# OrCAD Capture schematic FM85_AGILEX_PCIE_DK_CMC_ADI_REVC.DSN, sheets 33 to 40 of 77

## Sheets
33 FPGA BANK 15C: size B
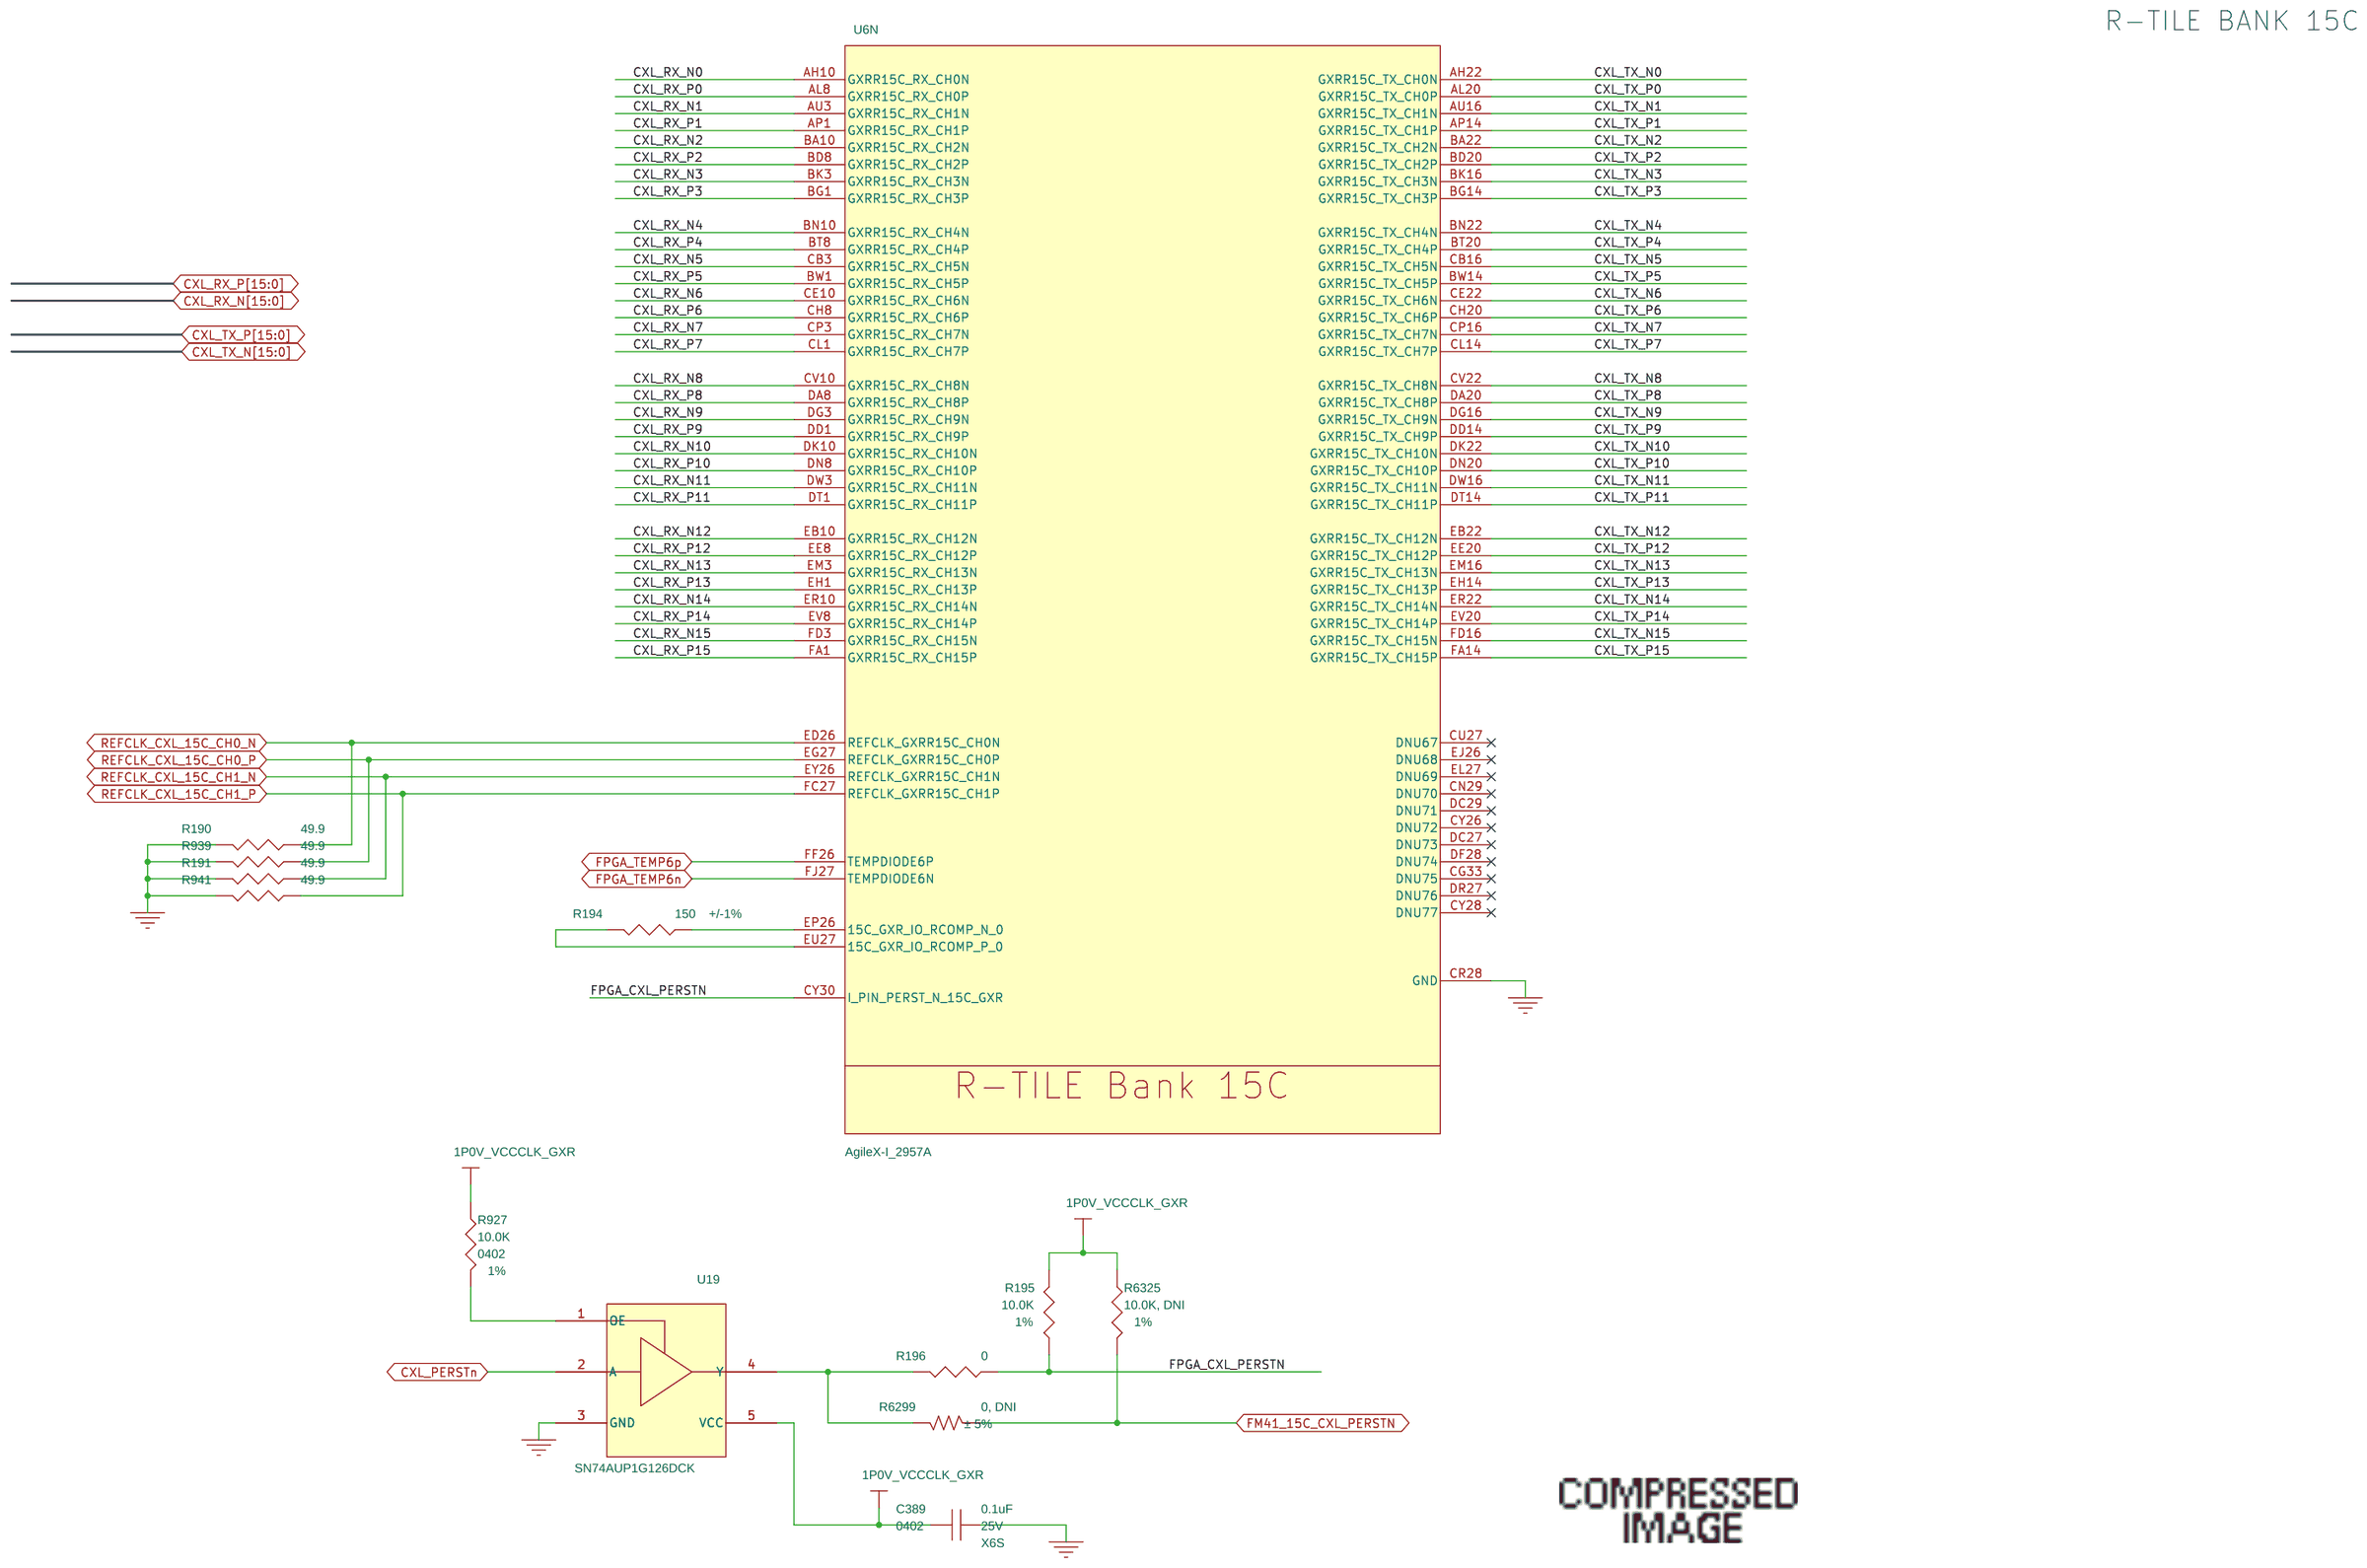
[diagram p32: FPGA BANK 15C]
34 FPGA BANK 15A: size B
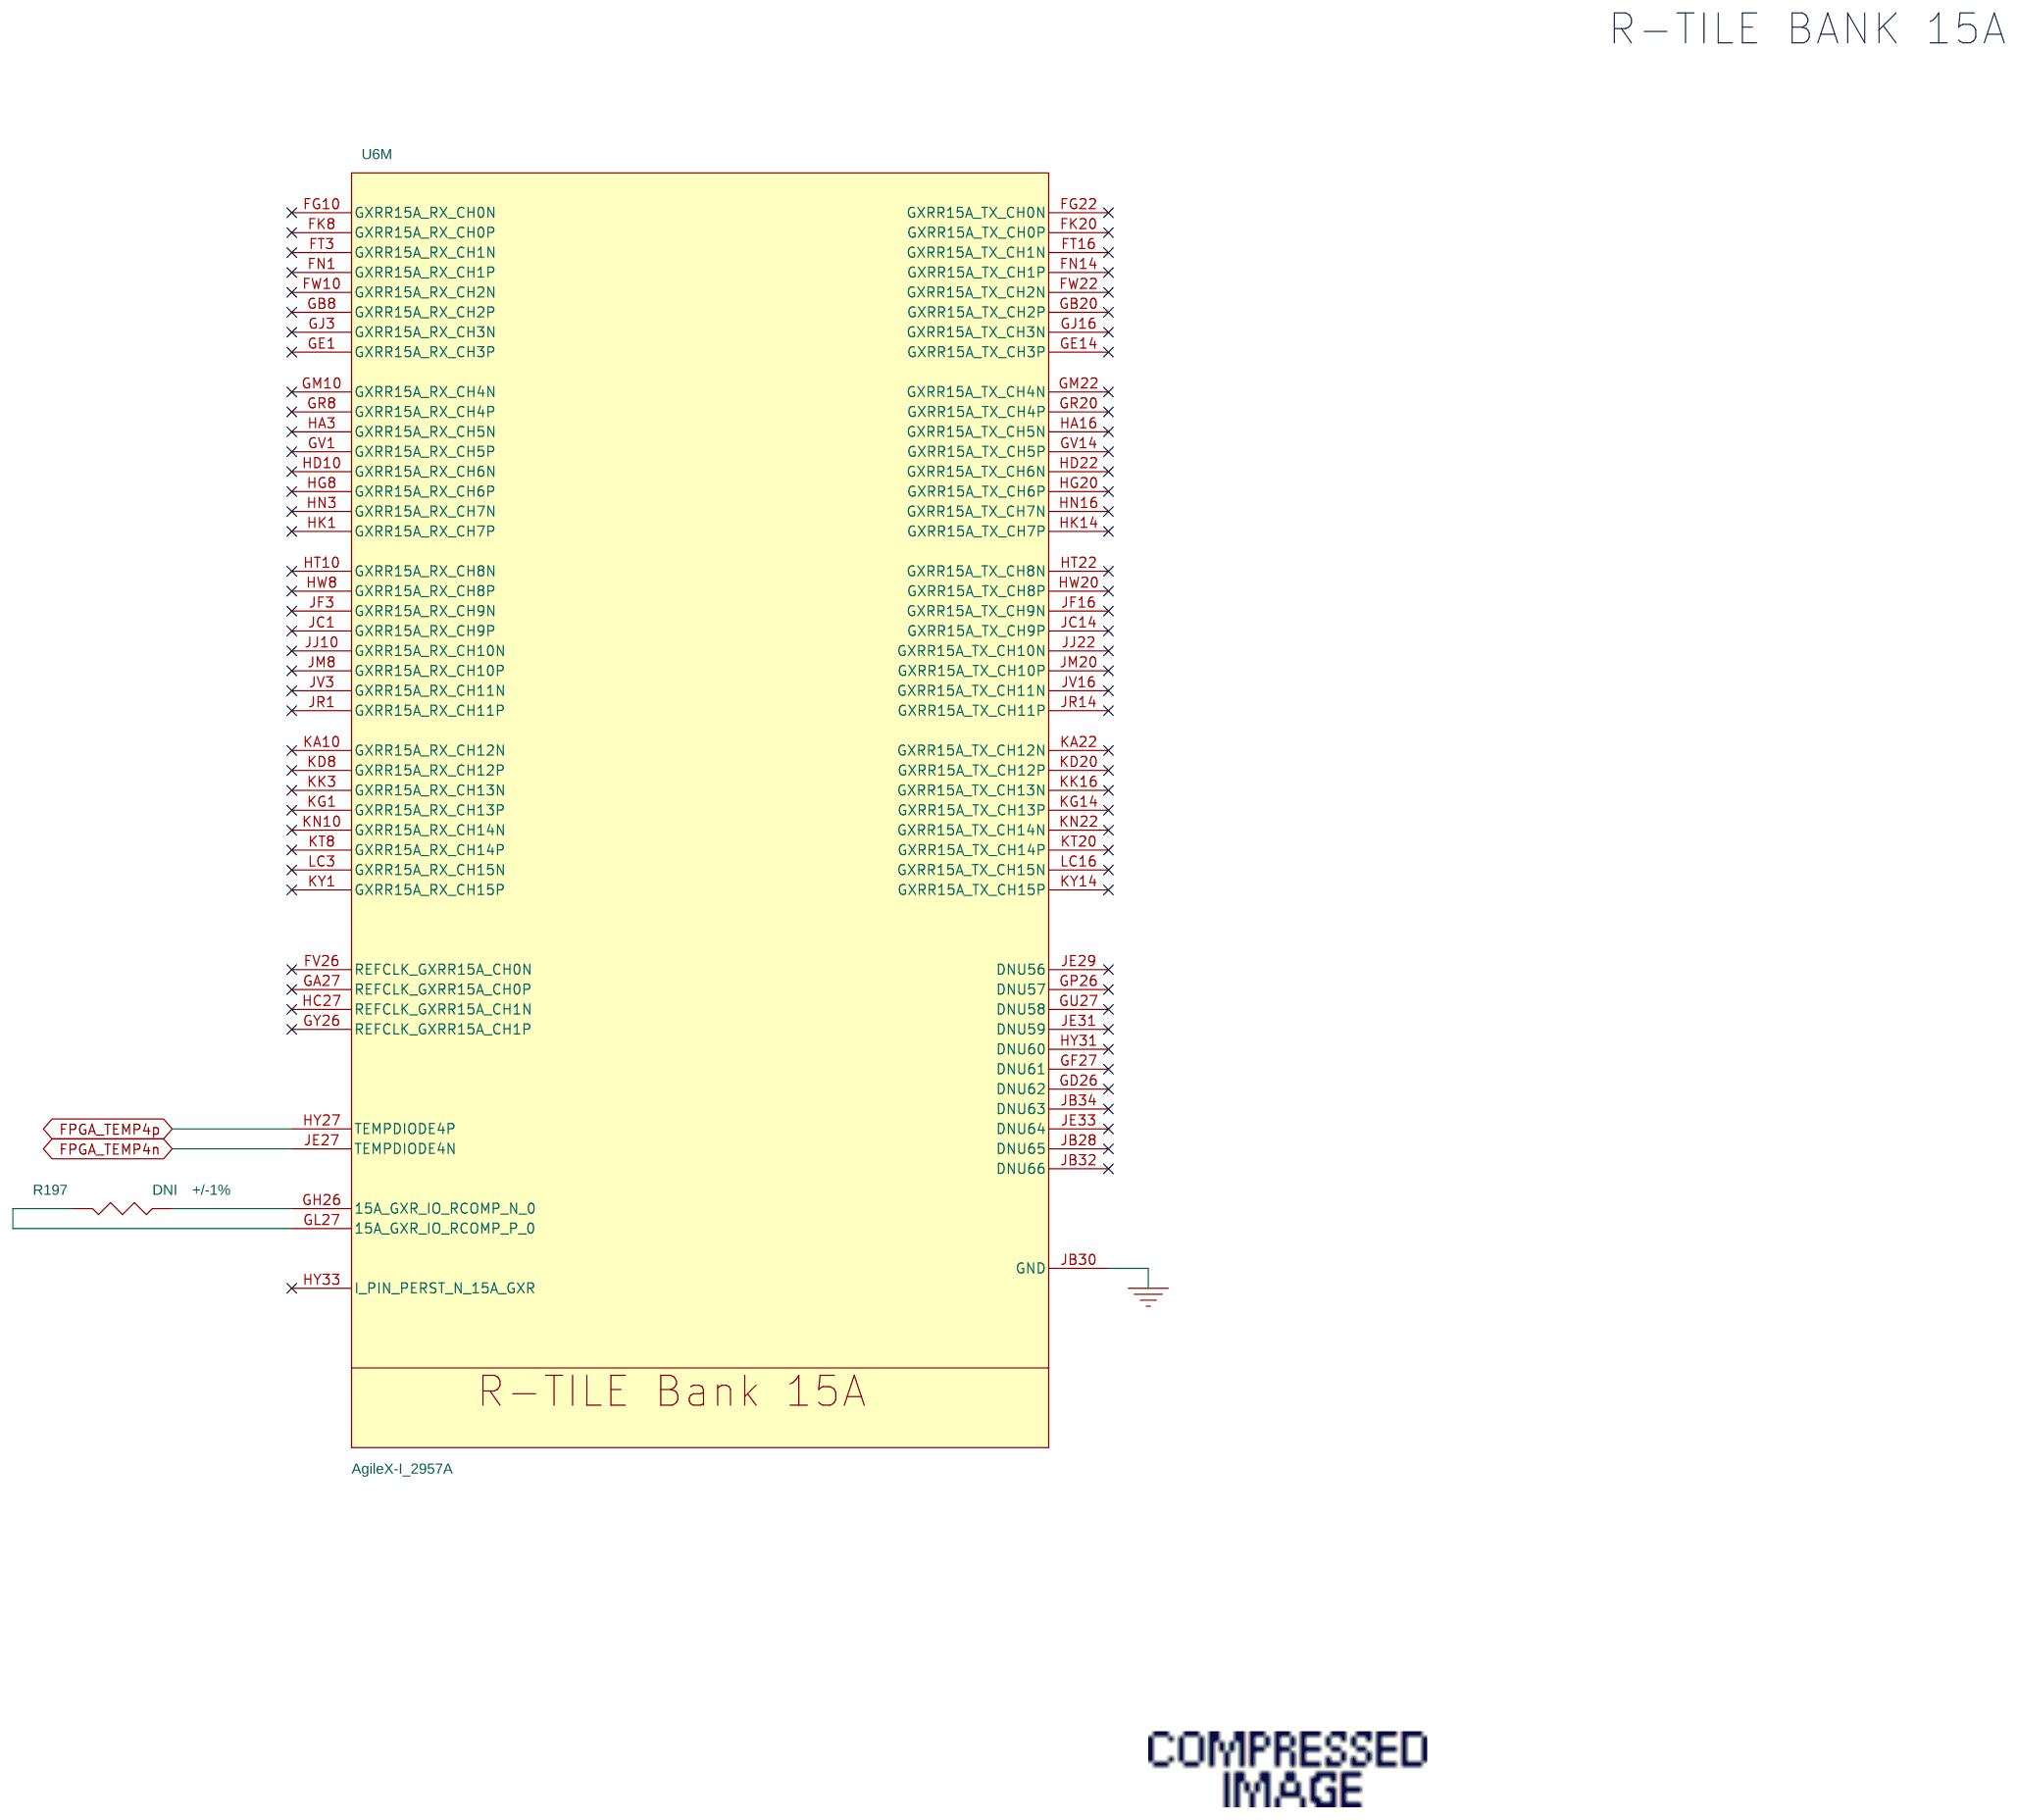
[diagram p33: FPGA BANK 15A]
35 FPGA BANK CONFIG SDM: size B
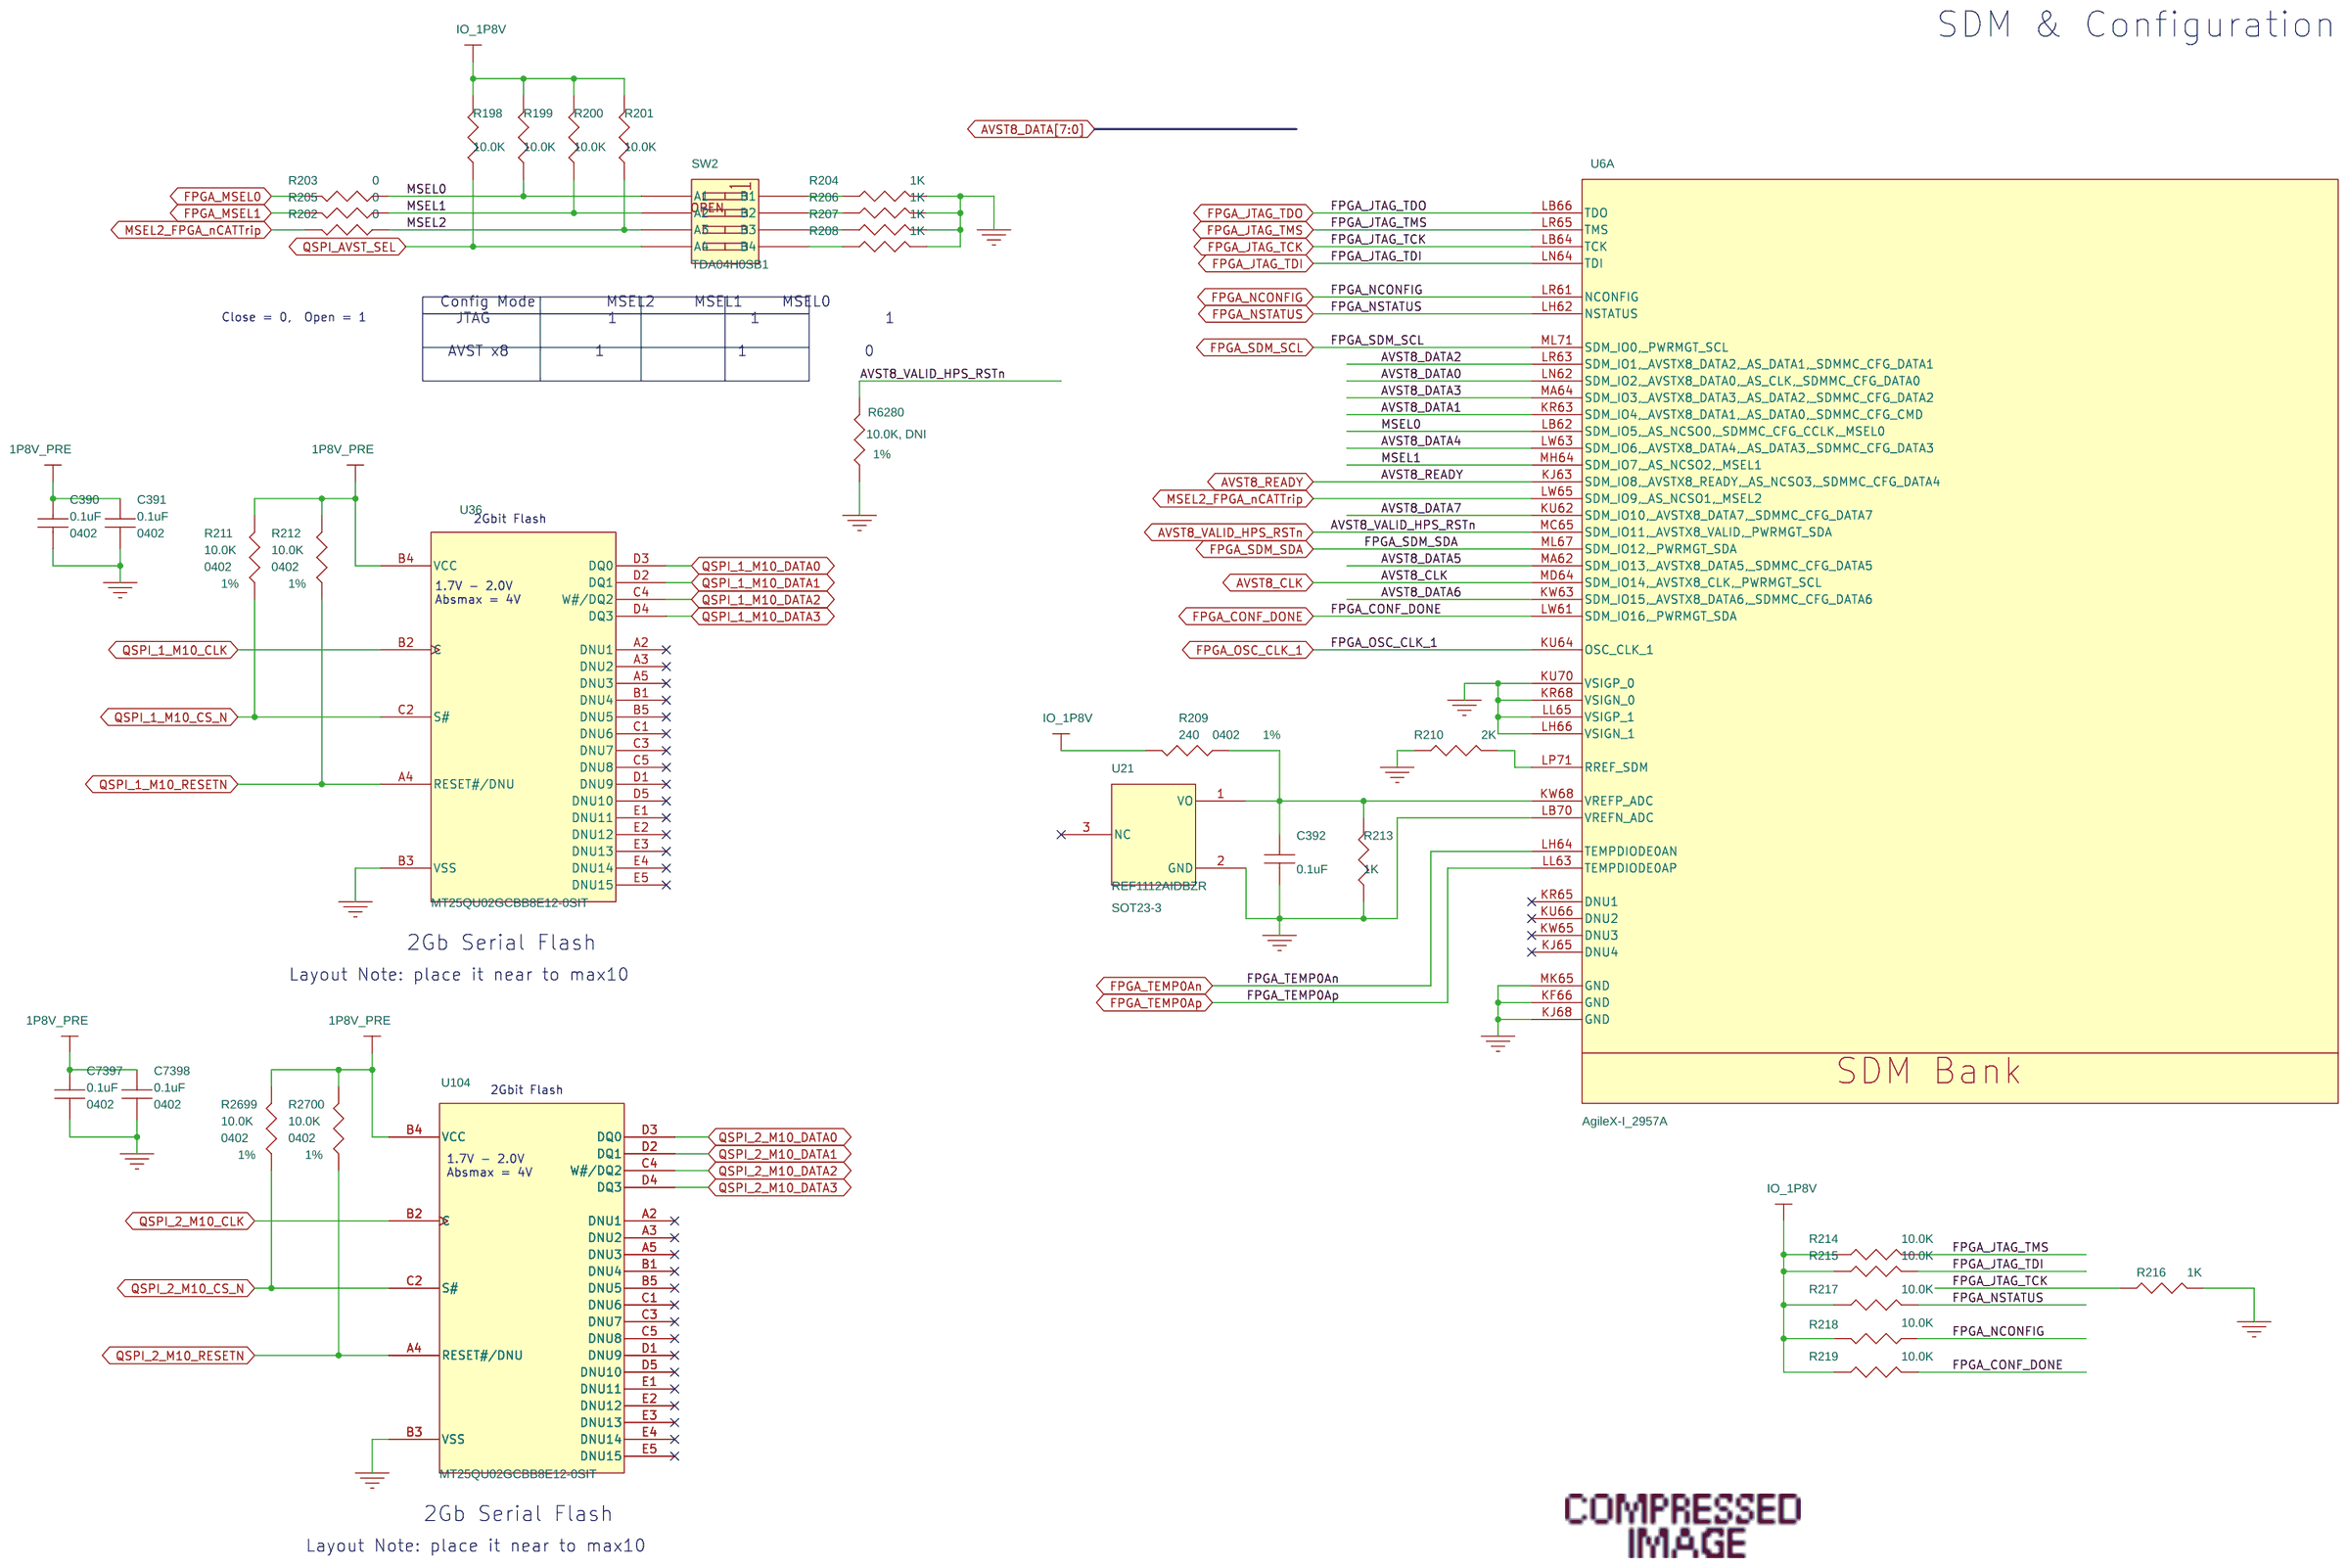
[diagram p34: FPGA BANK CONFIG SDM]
36 FPGA BANK HPS: size B
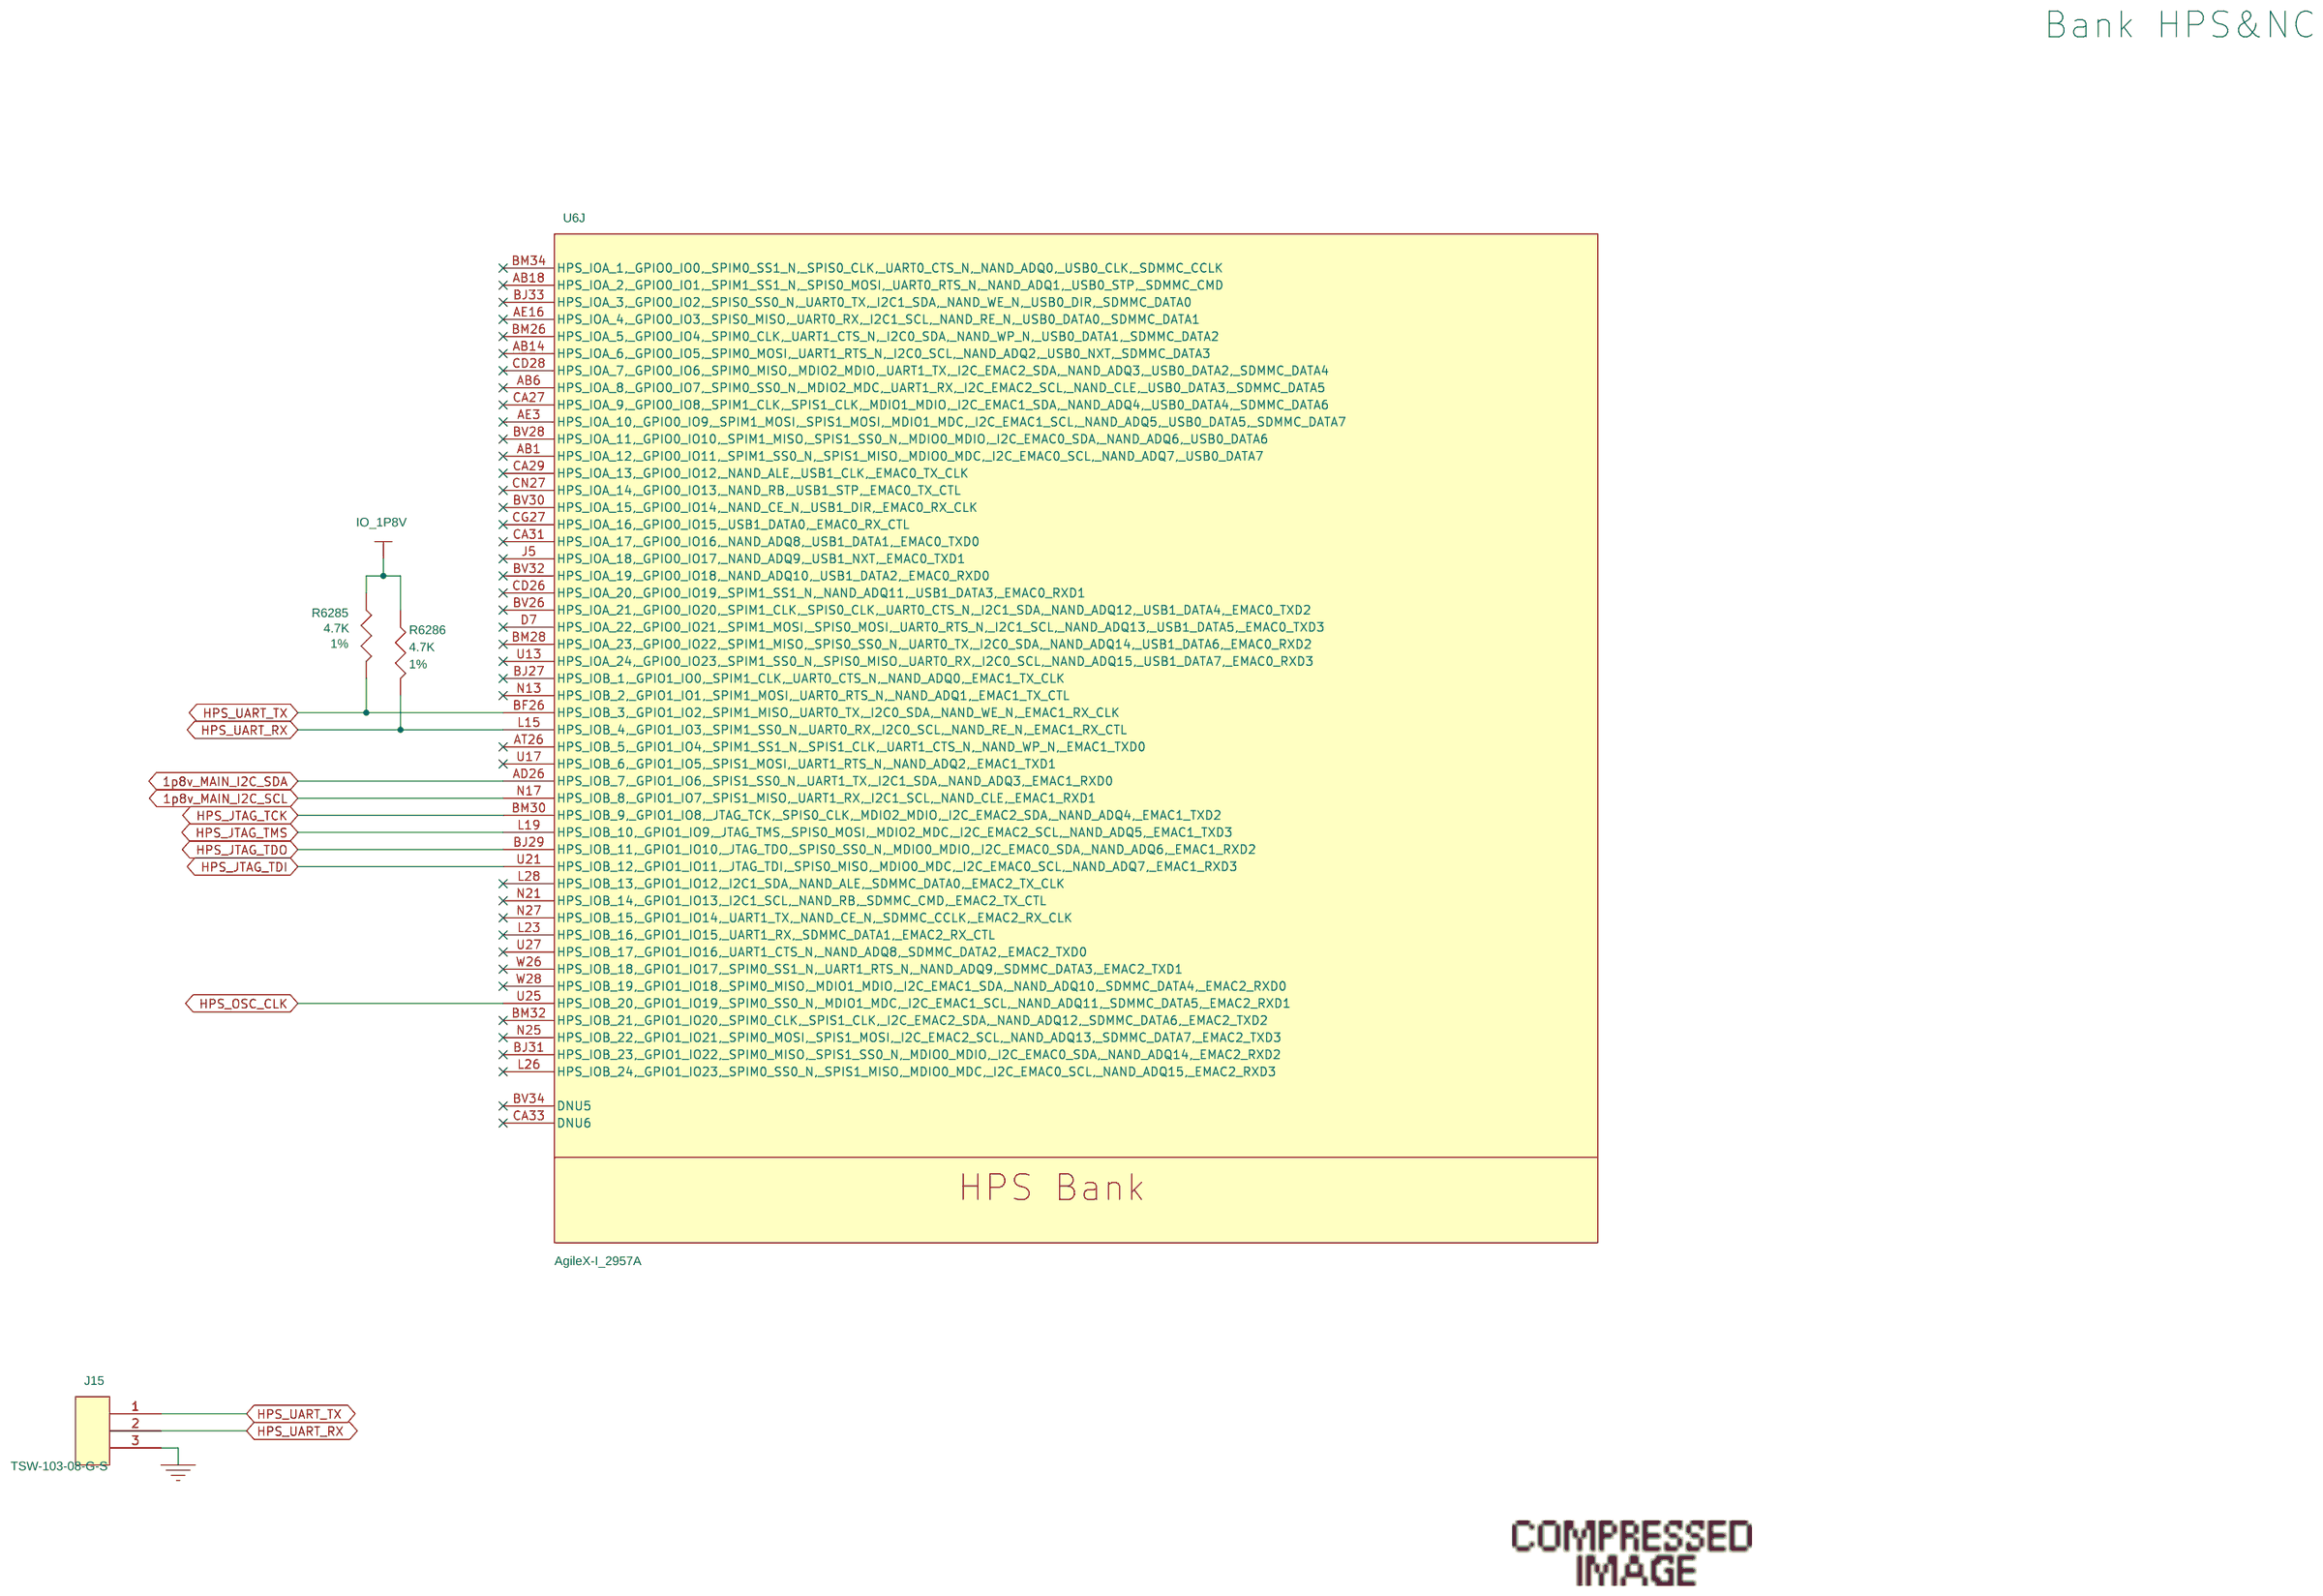
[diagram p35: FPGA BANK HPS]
37 FPGA Power 1: size B
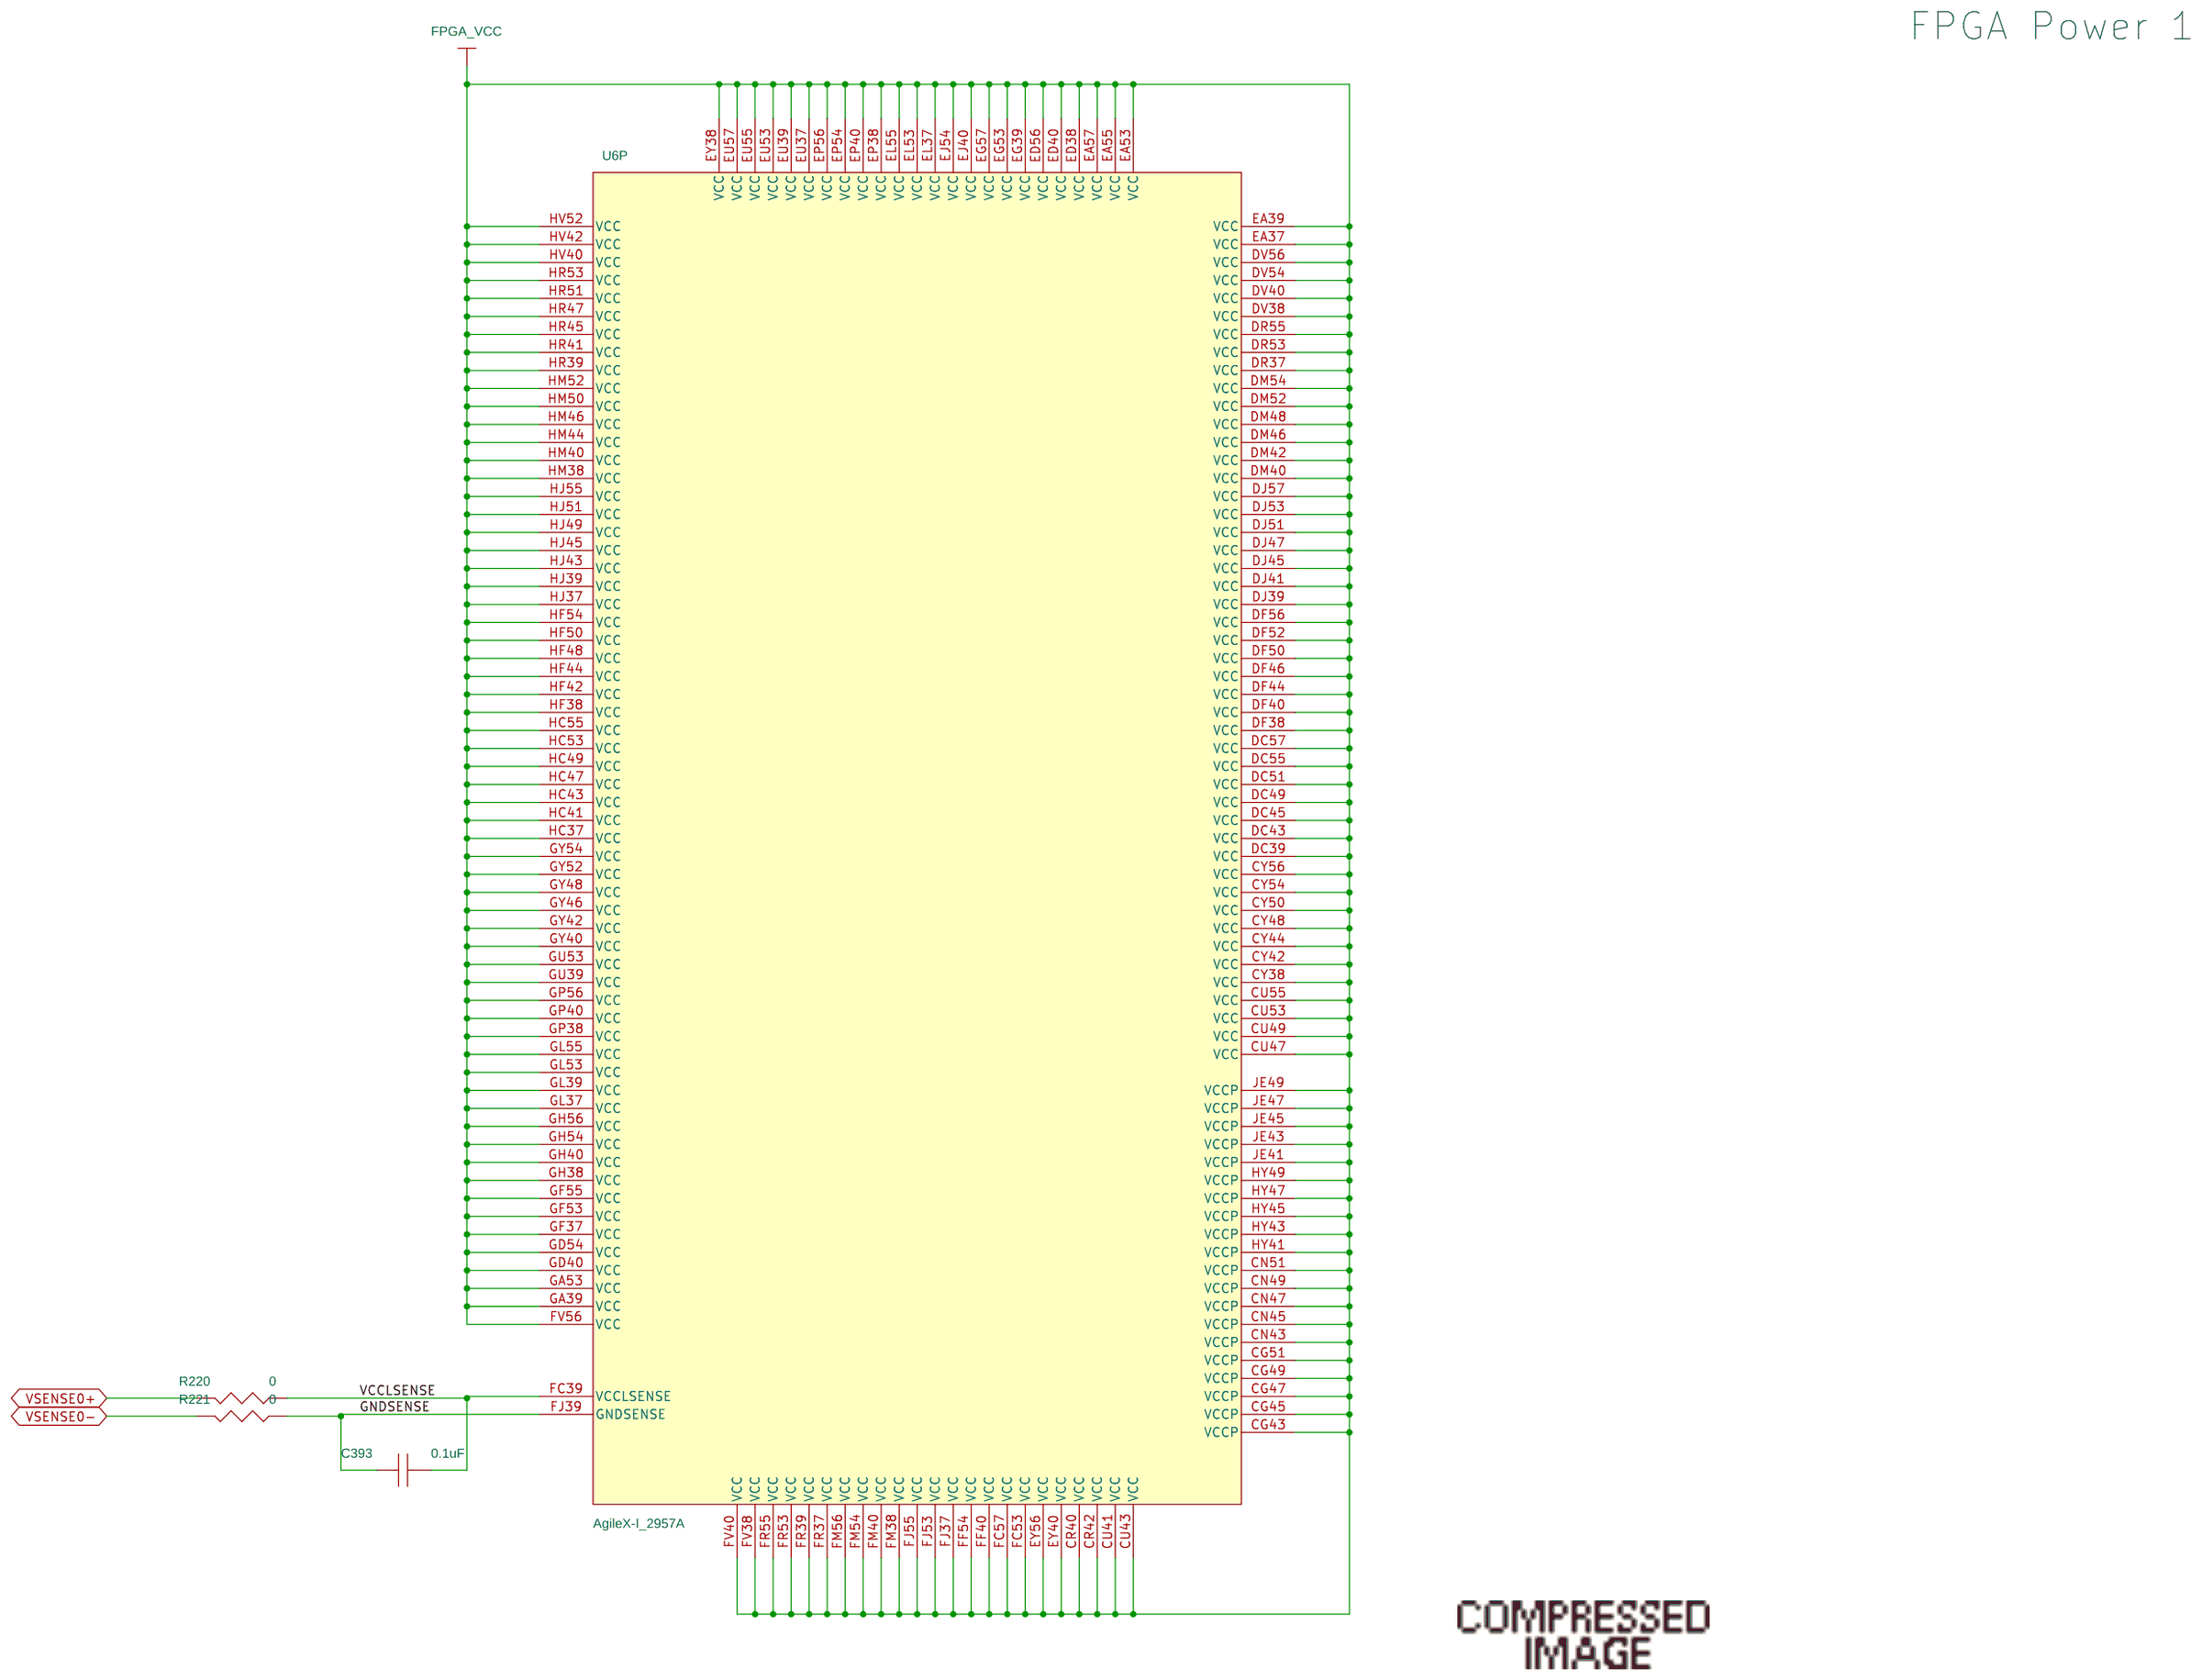
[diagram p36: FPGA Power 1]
38 FPGA Power 2: size B
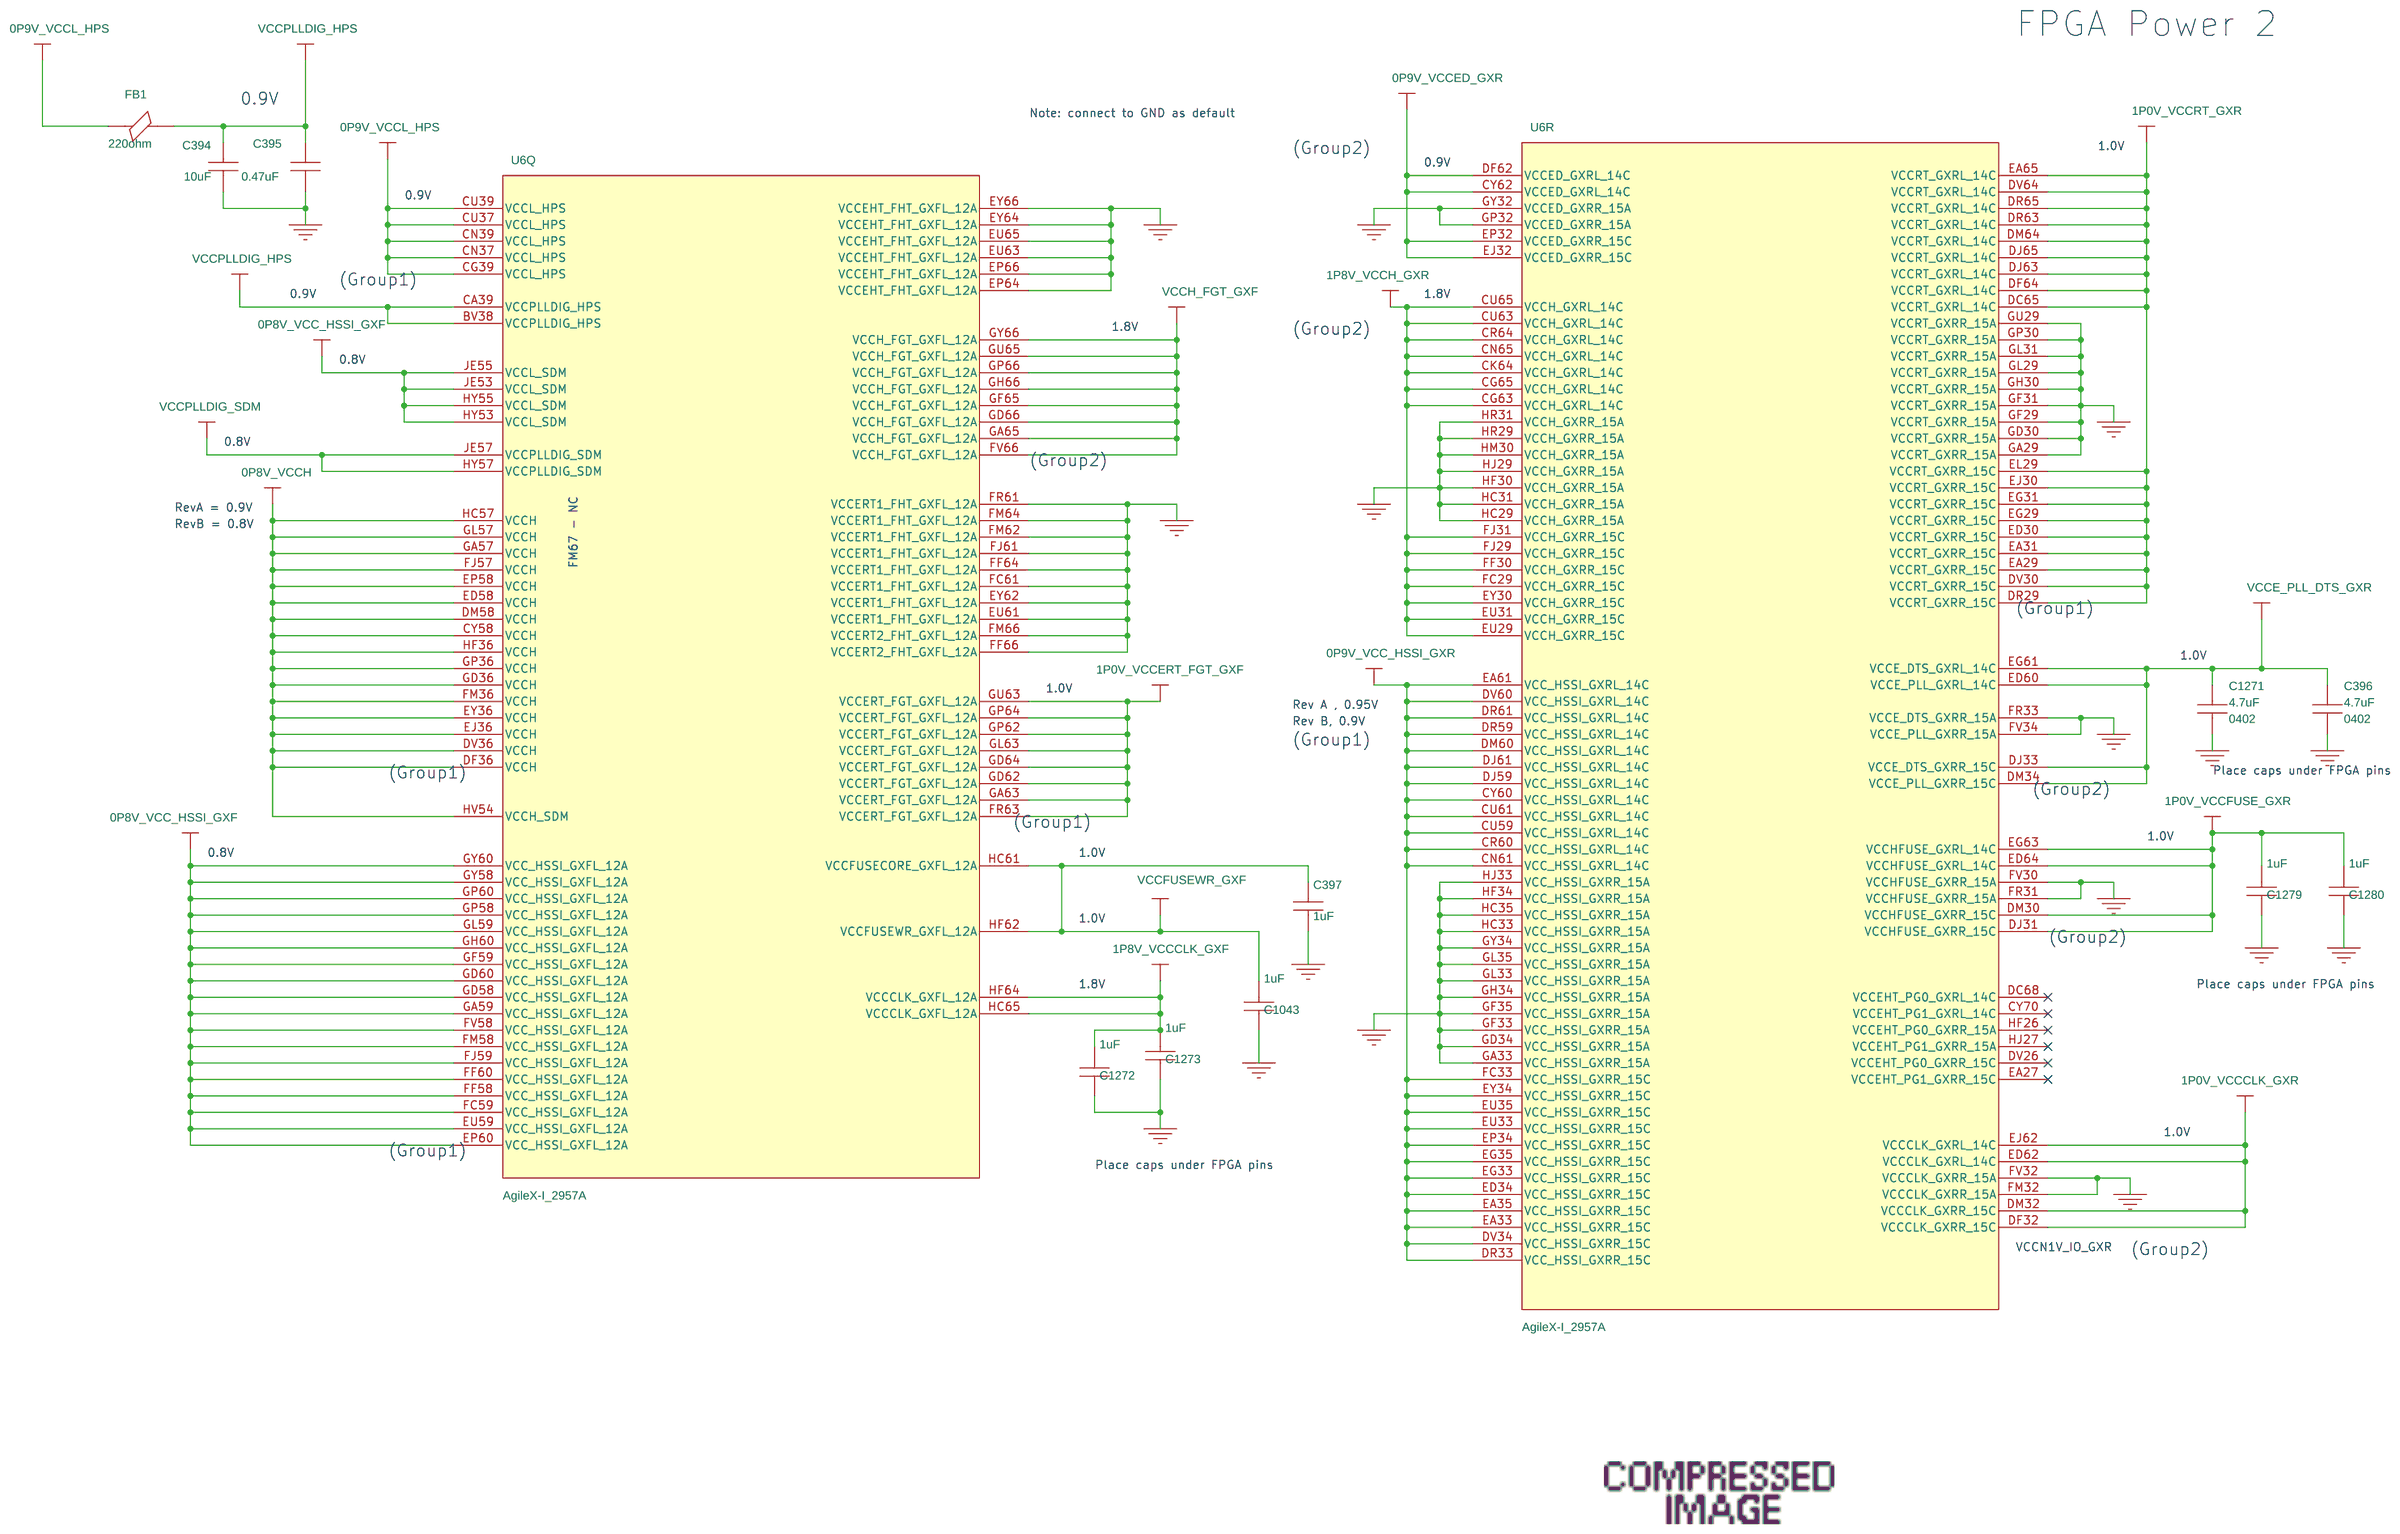
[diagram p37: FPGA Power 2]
39 FPGA Power 3: size B
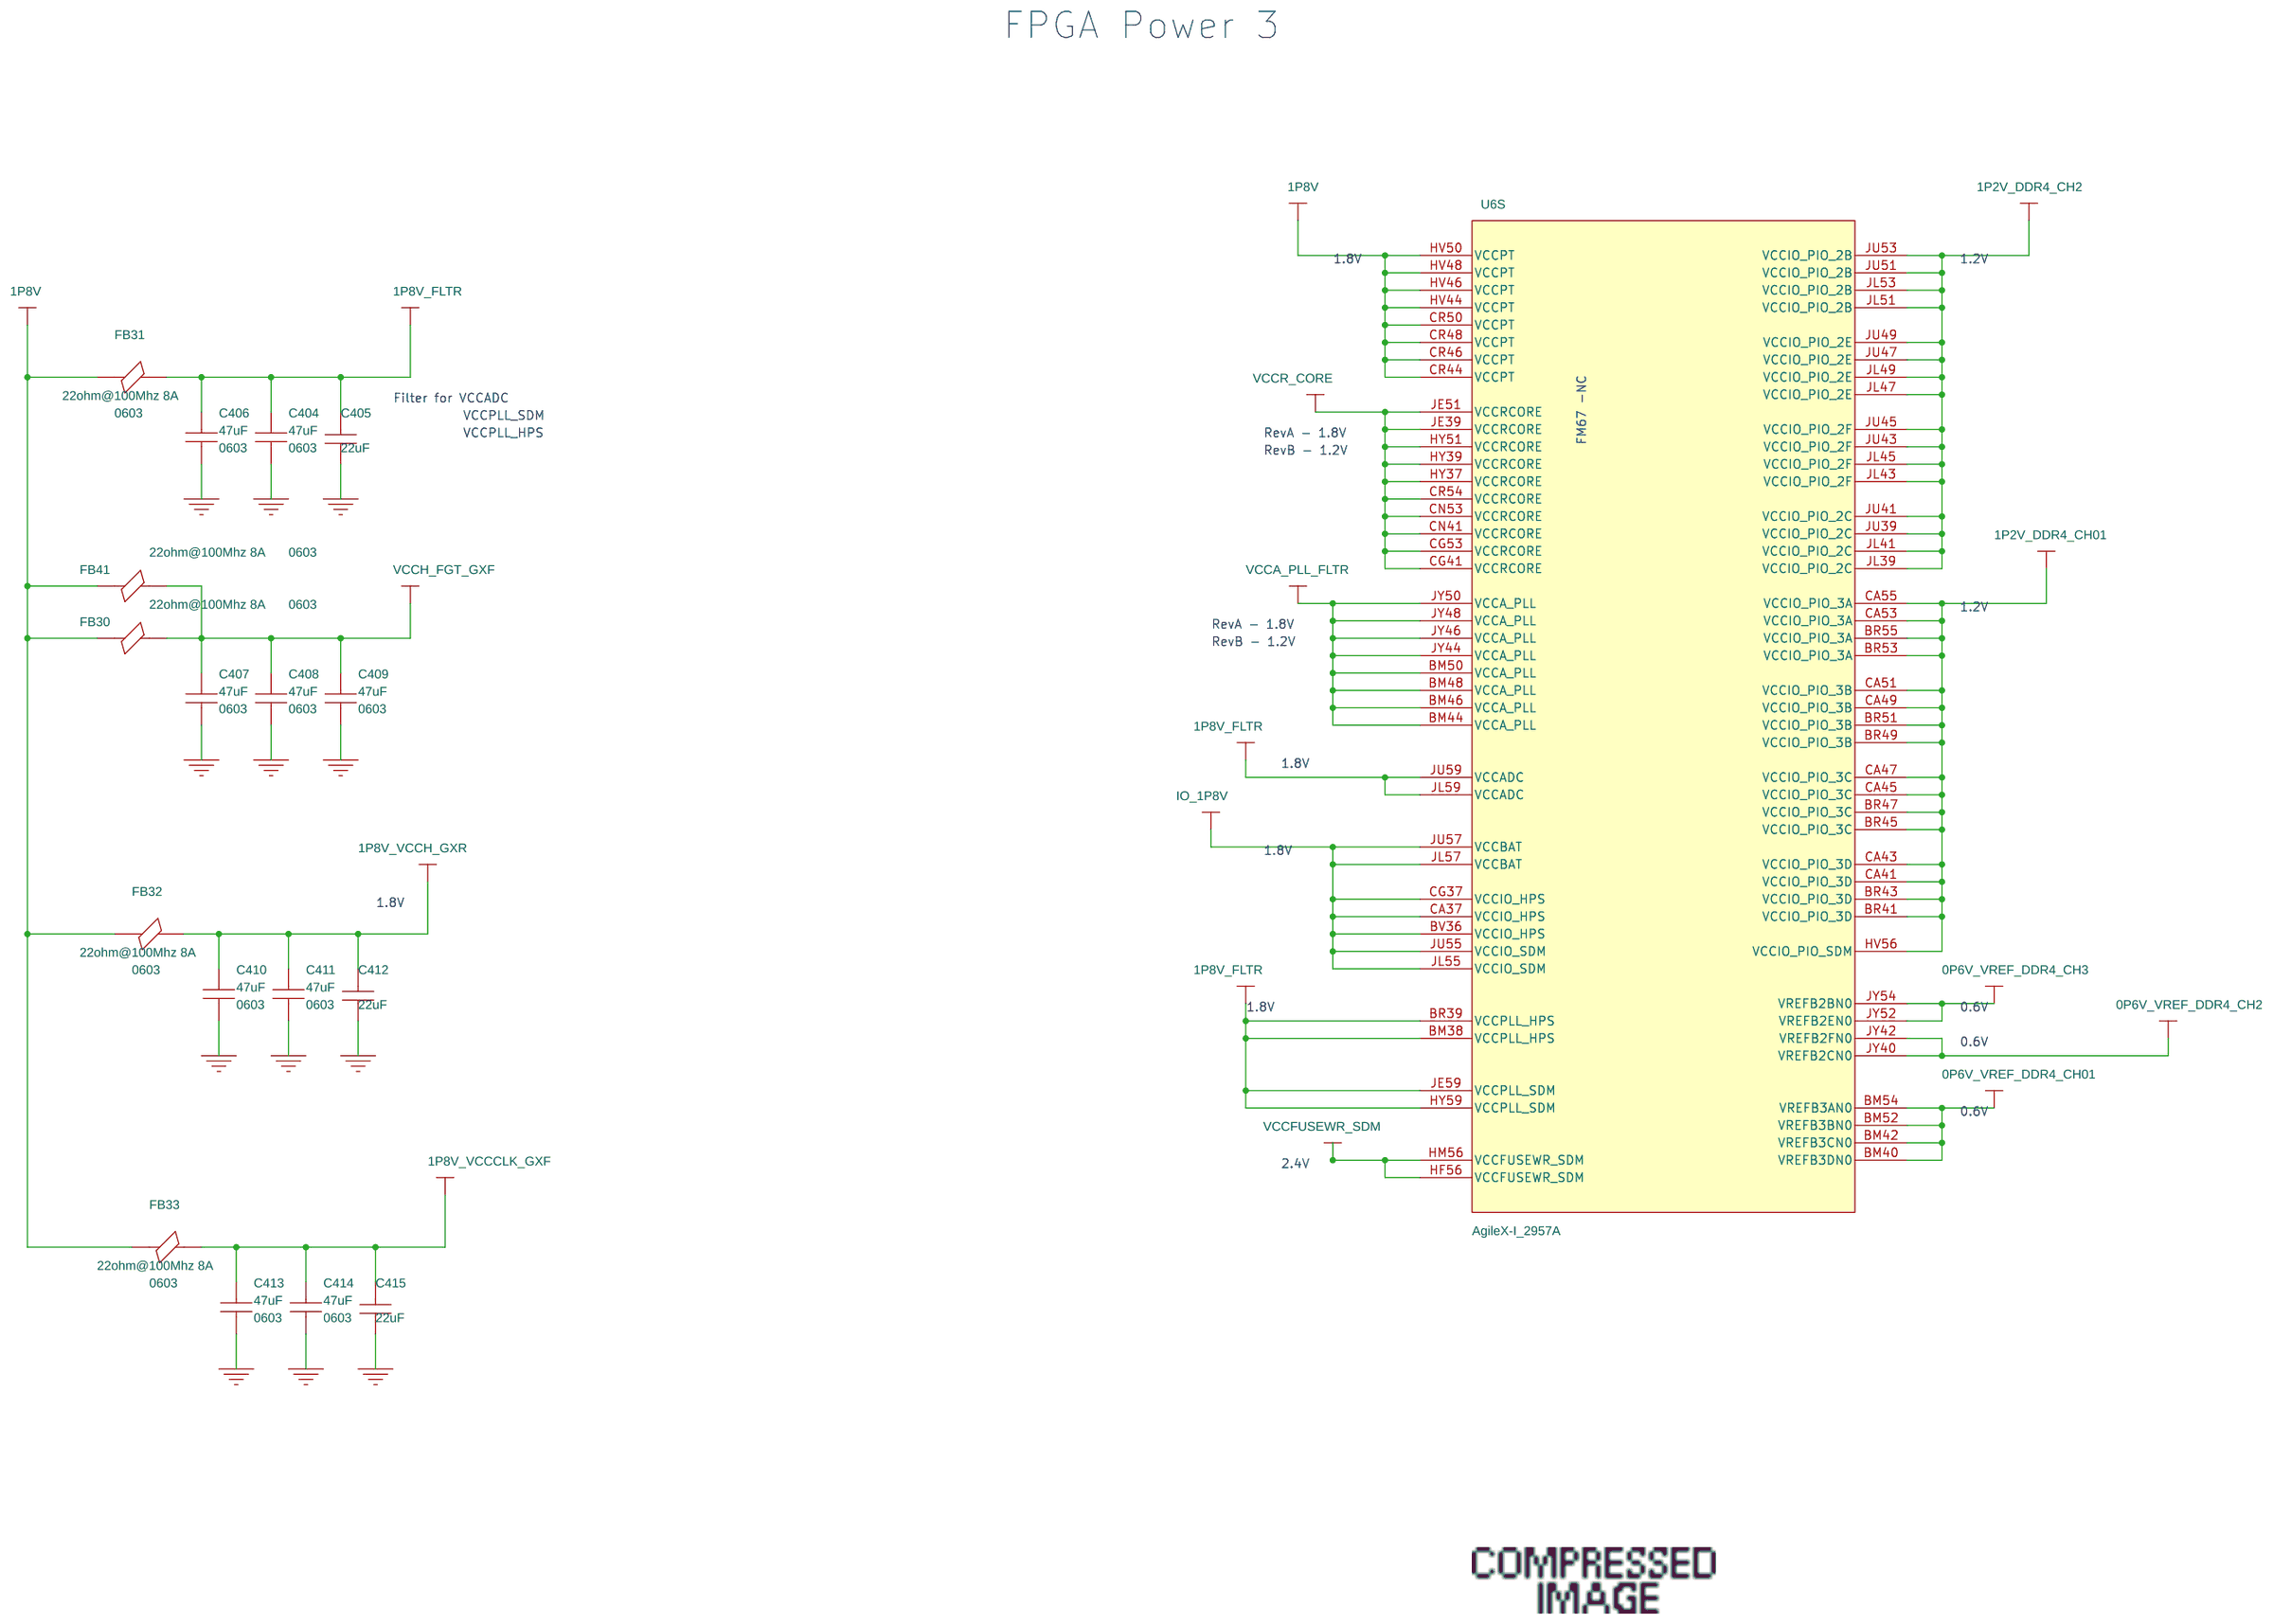
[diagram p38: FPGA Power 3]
40 FPGA Gnd 1: size B
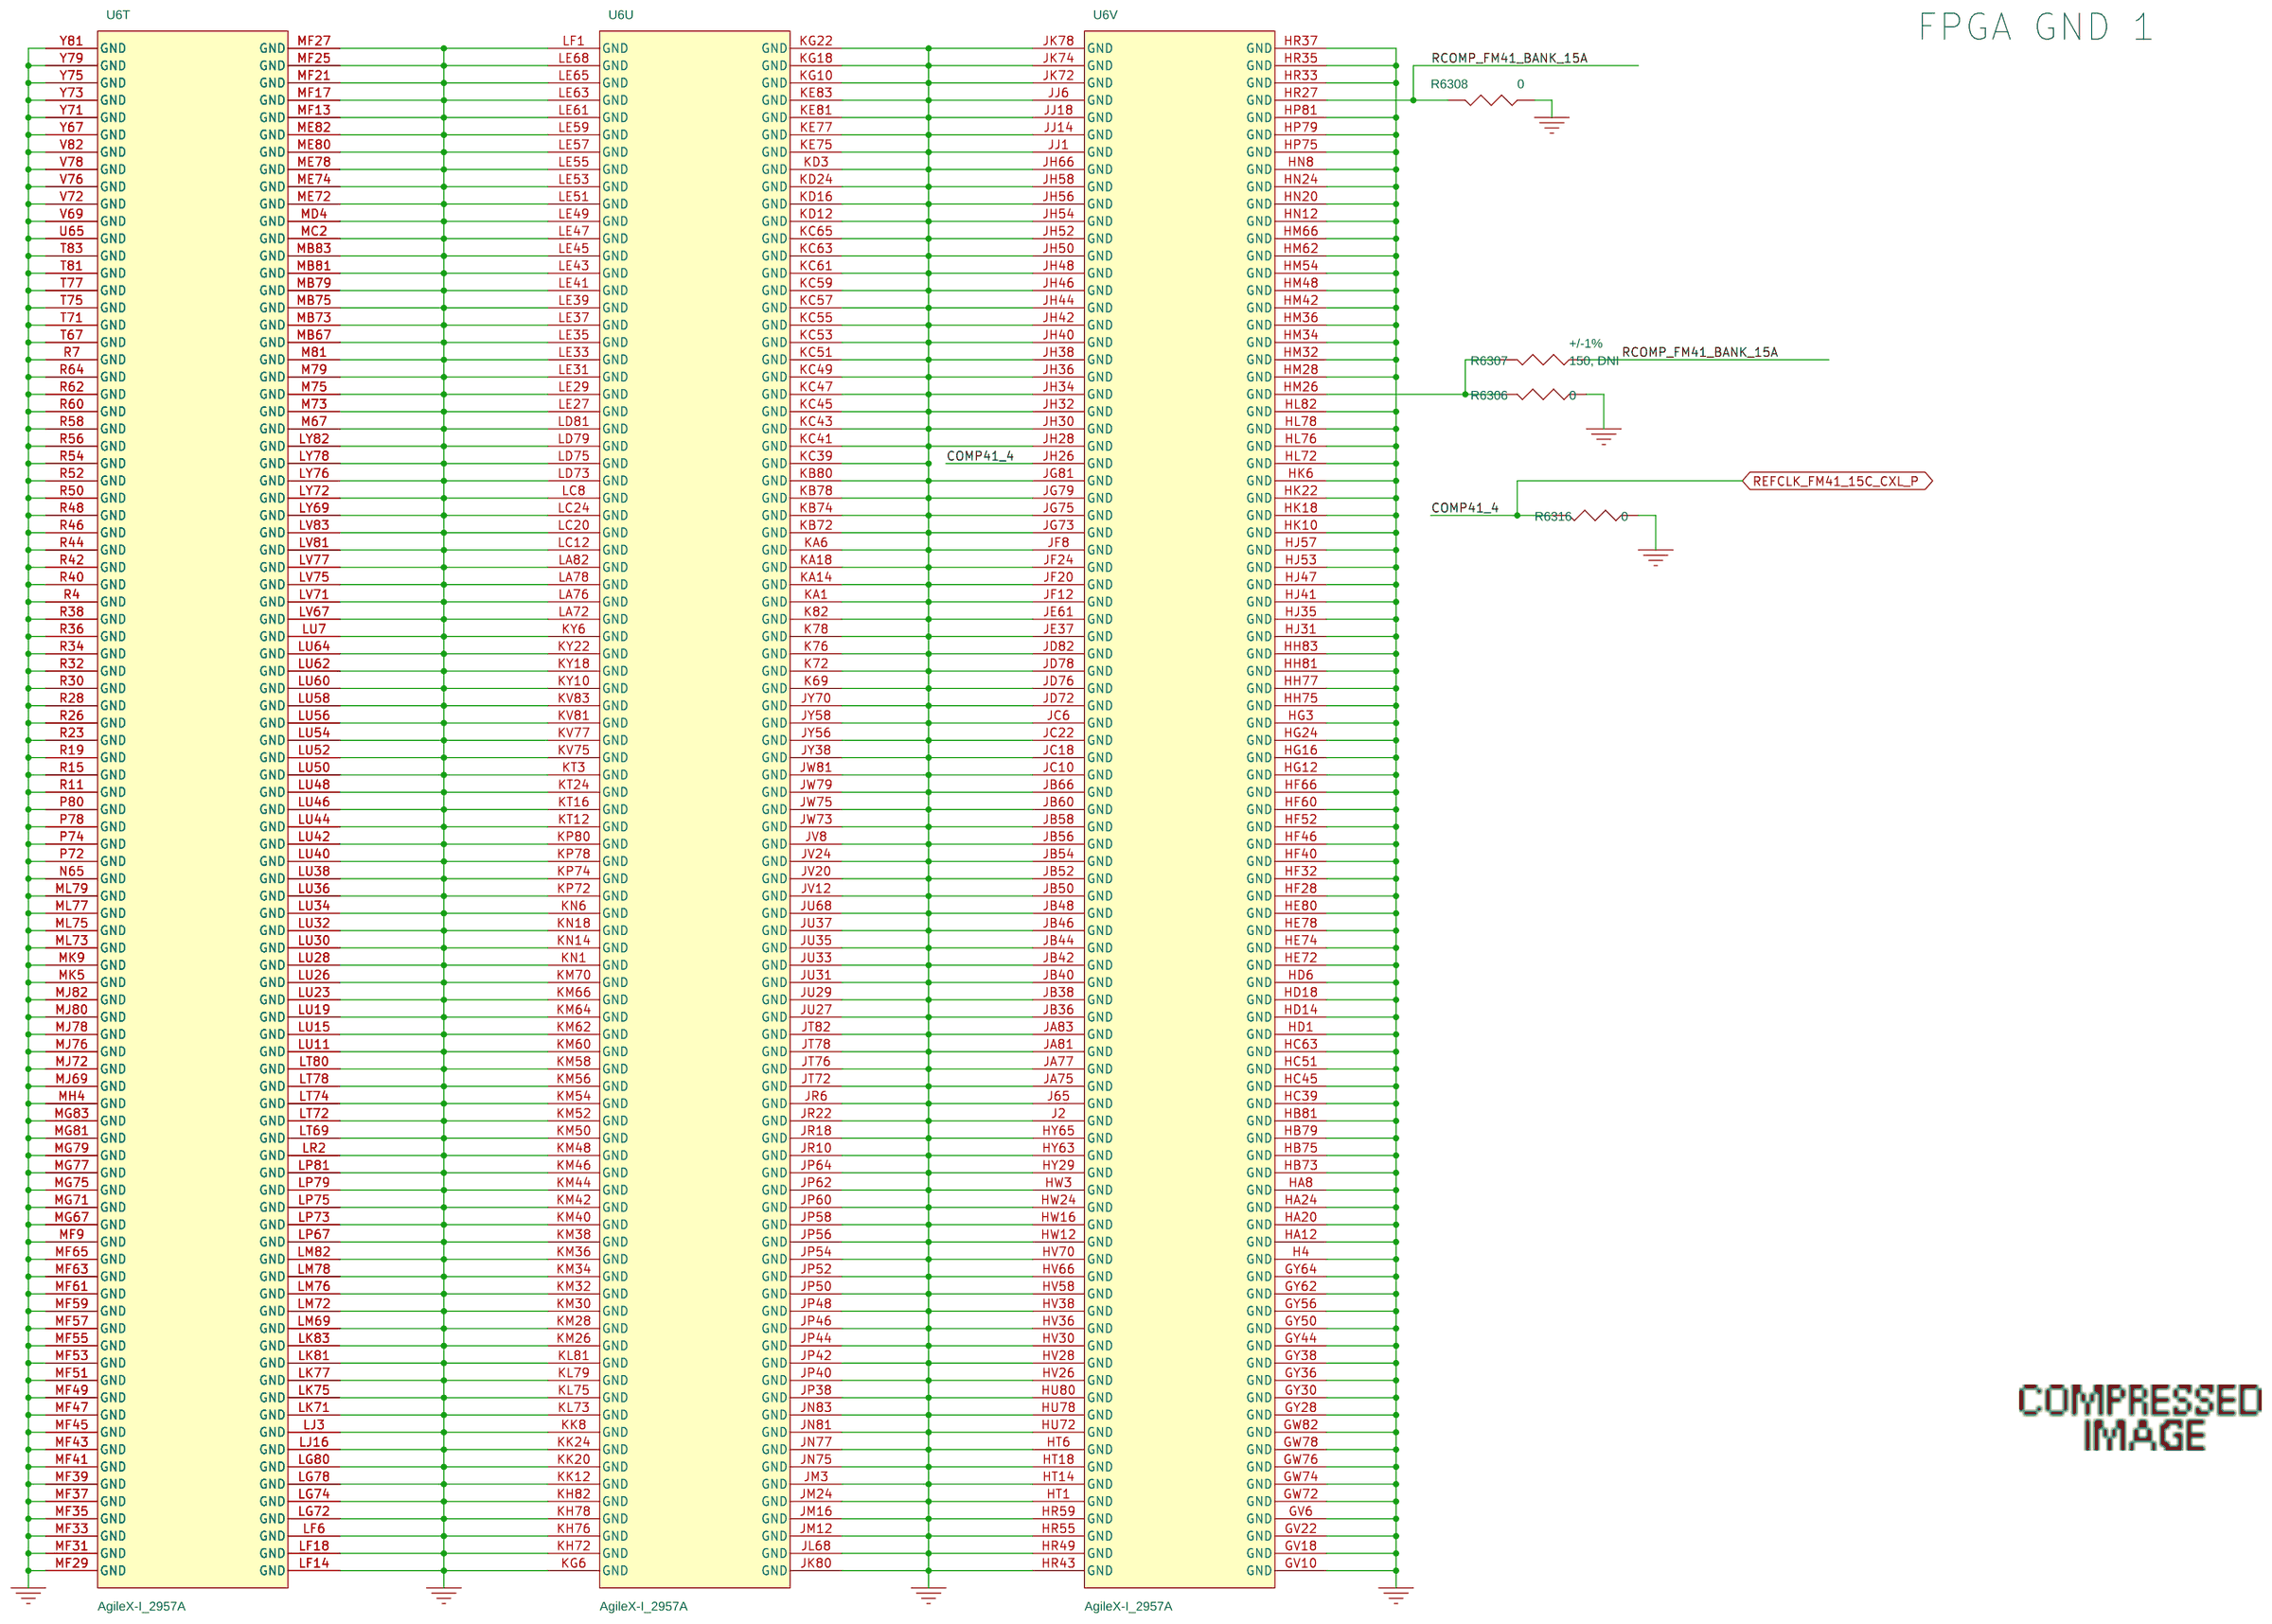
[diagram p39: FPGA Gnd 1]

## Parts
sheet FPGA BANK 2F
U6  AgileX-I_2957A  [fbga2957a_hex_p56x45]  (sections A,B,C,D,E,F,G,H,I,J,K,L,M,N,O,P,Q,R,S,T,U,V,W,X,Y,Z)
sheet FPGA BANK 15A
R197  DNI  [0402]
sheet FPGA BANK 15C
C389  0.1uF  [0402]
R190  49.9  [0402]
R191  49.9  [0402]
R194  150  [0402]
R195  10.0K  [0402]
R196  0  [0402]
R927  10.0K  [0402]
R939  49.9  [0402]
R941  49.9  [0402]
R6299  0, DNI  [RESC1005X40L20L]
R6325  10.0K, DNI  [0402]
U19  SN74AUP1G126DCK  [SC70_TI]
sheet FPGA BANK CONFIG SDM
C390  0.1uF  [0402]
C391  0.1uF  [0402]
C392  0.1uF  [0402]
C7397  0.1uF  [0402]
C7398  0.1uF  [0402]
R198  10.0K  [0402]
R199  10.0K  [0402]
R200  10.0K  [0402]
R201  10.0K  [0402]
R202  0  [0402]
R203  0  [0402]
R204  1K  [0402]
R205  0  [0402]
R206  1K  [0402]
R207  1K  [0402]
R208  1K  [0402]
R209  240  [0402]
R210  2K  [0402]
R211  10.0K  [0402]
R212  10.0K  [0402]
R213  1K  [0402]
R214  10.0K  [0402]
R215  10.0K  [0402]
R216  1K  [0402]
R217  10.0K  [0402]
R218  10.0K  [0402]
R219  10.0K  [0402]
R2699  10.0K  [0402]
R2700  10.0K  [0402]
R6280  10.0K, DNI  [0402]
SW2  TDA04H0SB1  [DIPSWITCH_SMT_QUAD]
U21  REF1112AIDBZR  [SOT23-3]
U36  MT25QU02GCBB8E12-0SIT  [T-PBGA24]
U104  MT25QU02GCBB8E12-0SIT  [T-PBGA24]
sheet FPGA BANK HPS
J15  TSW-103-08-G-S  [1x3_HDR_TH]
R6285  4.7K  [0402]
R6286  4.7K  [0402]
sheet FPGA Gnd 1
R6306  0  [0402]
R6307  150, DNI  [0402]
R6308  0  [0402]
R6316  0  [0402]
sheet FPGA Power 1
C393  0.1uF  [0402]
R220  0  [0402]
R221  0  [0402]
sheet FPGA Power 2
C394  10uF  [0603]
C395  0.47uF  [0402]
C396  4.7uF  [0402]
C397  1uF  [0201]
C1043  1uF  [0201]
C1271  4.7uF  [0402]
C1272  1uF  [0201]
C1273  1uF  [0201]
C1279  1uF  [0201]
C1280  1uF  [0201]
FB1  220ohm  [0402]
sheet FPGA Power 3
C404  47uF  [0603]
C405  22uF  [0603]
C406  47uF  [0603]
C407  47uF  [0603]
C408  47uF  [0603]
C409  47uF  [0603]
C410  47uF  [0603]
C411  47uF  [0603]
C412  22uF  [0603]
C413  47uF  [0603]
C414  47uF  [0603]
C415  22uF  [0603]
FB30  22ohm@100Mhz 8A  [0603]
FB31  22ohm@100Mhz 8A  [0603]
FB32  22ohm@100Mhz 8A  [0603]
FB33  22ohm@100Mhz 8A  [0603]
FB41  22ohm@100Mhz 8A  [0603]

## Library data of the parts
U6 = AgileX-I_2957A: Item Num: 99C7VA
R194 R197 R6307 = RESISTOR: RES,150 OHMS,1.0%,1/16W,0402; Item Num: G60609-012; Manufacturer: Yageo; Manufacturer Part Num: RC0402FR-07150RL; Num Pins: 2; Part Class: RESISTORS; TOLERANCE: +/-1%
C389 = CAP: CAP CER 0.1UF 25V X6S 0402; Dielectric: X6S; Item Num: K19434-001; LIFECYCLE_PHASE: Active; Lead Free Status: Lead Free; Manufacturer: Murata; Manufacturer Part Num: GRM155C81E104KA12D; Num Pins: 2; Part Class: CAPACITORS; RATED_VOLTAGE: 25V; RoHS Compliant: RoHS Compliant; Tolerance: 10%
R190 R191 R939 R941 = RESISTOR: RES, 49.9 OHMS, 1%, 1/16W, 0402; Item Num: K16545-001; Lead Free Status: Yes; Manufacturer: NIC Components Corp.; Manufacturer Part Num: NRC04F49R9TRF; Num Pins: 2; Part Class: Resistors; Price: 0
R195 R211 R212 R927 R2699 R2700 R6280 R6325 = RESISTOR: RES,10.0K OHMS,1.0%,1/16W, 0402; AGILE_LINK: http://sj-agile9app/Agile/PLMServlet?action=OpenEmailObject&classid=10000&objid=146548997; Item Num: K28115-001; LIFECYCLE_PHASE: Active; Lead Free Status: No; MFR_LIFECYCLE: Active; Manufacturer: Panasonic; Manufacturer Part Num: ERJ-2RKF1002X; Num Pins: 2; PART_SUBCLASS: RESISTORS; POWER: 1/16W; RESISTANCE: 10K; RoHS Compliant: Yes; TOLERANCE: 1%
R196 R202 R203 R205 R6306 R6308 R6316 = RESISTOR: RES ZERO OHM 1/16W 5% 0402 SMD; Agile IPN: P02-14020R; Altera Part No.: P02-14020R; Item Num: H30887-001; Lead Free Status: No; Manufacturer: Panasonic; Manufacturer Part Num: ERJ-2GE0R00X; Num Pins: 2; Part Class: RESISTORS; RoHS Compliant: Yes; Tolerance: 5%
R6299 = Resistor,_0402_0: RES D,0402,0.00 OHM,5.00%,1/16W; Agile Part Number: 02495; Item Num: A93549-001; Manufacturer: YAGEO CORP.; Manufacturer Part Num: ERJ-2GE0R00X; Package: 0402; Part Number: ERJ-2GE0R00X; Tolerance: ± 5%
U19 = SN74AUP1G126DCK: IC - LOW-POWER SINGLE BUS BUFFER GATE WITH 3-STATE OUTPUT 3.6-V I/O TOLERANT; Item Num: K14022-001; Manufacturer: Texas Instruments; Manufacturer Part Num: SN74AUP1G126DCKT
C390 C391 C7397 C7398 = CAP: CAPC,  X7R, 0402, 0.1uF, 25V, ±20%; Dielectric: X7R; Item Num: K13660-001; LIFECYCLE_PHASE: Active; Lead Free Status: Lead Free; Manufacturer: TDK Corporation; Manufacturer Part Num: CGA2B3X7R1E104K050BB; Num Pins: 2; Part Class: CAPACITORS; Price: 0.07; RATED_VOLTAGE: 25V; RoHS Compliant: RoHS Compliant; Tolerance: ±10%
C392 = CAP: CAPC,  X7R, 0402, 0.1uF, 25V, ±20%; Dielectric: X5R; Item Num: K13660-001; LIFECYCLE_PHASE: Active; Lead Free Status: Lead Free; Manufacturer: TDK Electronics; Manufacturer Part Num: C1005X7R1E104M; Num Pins: 2; Part Class: CAPACITORS; Price: 0.07; RoHS Compliant: RoHS Compliant; Tolerance: +80%/-20%
R198-R201 R214 R215 R217-R219 = RESISTOR: RES,10.0K OHMS,1.0%,1/16W, 0402; AGILE_LINK: http://sj-agile9app/Agile/PLMServlet?action=OpenEmailObject&classid=10000&objid=146548997; Item Num: K28115-001; LIFECYCLE_PHASE: Active; Lead Free Status: No; MFR_LIFECYCLE: Active; Manufacturer: Panasonic; Manufacturer Part Num: ERJ-2RKF1002X; Num Pins: 2; PART_SUBCLASS: RESISTORS; POWER: 1/16W; RoHS Compliant: Yes; TOLERANCE: +/-1%
R204 R206-R208 R213 R216 = RESISTOR: RES,1.00K OHMS,1.0%,1/16W,0402; Item Num: G60609-021; Lead Free Status: No; Manufacturer: Panasonic; Manufacturer Part Num: ERJ-2RKF1001X; Num Pins: 2; Part Class: Resistors
R209 = RESISTOR: RES - 240 OHM, 1/16W, 1%, 0402 SMD; Item Num: K15783-001; Lead Free Status: No; Manufacturer: Panasonic; Manufacturer Part Num: ERJ-2RKF2400X; Num Pins: 2; Part Class: Resistors; TOLERANCE: 1%
R210 = RESISTOR: RES,2.00K OHMS,1.0%,1/16W,0402; Item Num: J43524-001; Lead Free Status: Yes; Manufacturer: Panasonic; Manufacturer Part Num: ERJ-2RKF2001X; Num Pins: 2; Part Class: RESISTORS; Price: 0; RoHS Compliant: Yes
SW2 = SPST4: SWITCHES - 4 POS, 8 PIN, Ultra-mini SMT Half-pitch Slider DIP Switch; Item Num: K15518-001; Lead Free Status: Yes; Manufacturer: C & K Components/ITT Industries; Num Pins: 8; Part Class: Switches; Price: 0; RoHS Compliant: Yes; Supplier: 8
U21 = REF1112: IC VREF SHUNT 1.25V SOT23-3; Item Num: K21883-001; Manufacturer: Texas Instruments
U36 = MT25QU01GBBB: SERIAL_NOR FLASH,2GBIT,1.8V,,TBGA24; Item Num: K14016-001; Manufacturer: Micron; Part_Number: ICM000214
U104 = MT25QU01GBBB: IC Flash SPI 2Gbit NOR 1.7–2.0V Reset&Hold BGA24; Item Num: K14016-001; Manufacturer: Micron; Part_Number: ICM000214
J15 = 1x3_HDR_TH: 1X3 .100"CENTER HDR,.145" MIN SOLDER TAIL; Item Num: K12462-001; Manufacturer: SAMTEC
R6285 R6286 = RESISTOR: RES,4.70K OHMS,1.0%,1/16W,0402; AGILE_LINK: http://sj-agile9app/Agile/PLMServlet?action=OpenEmailObject&classid=10000&objid=146753272; Item Num: D60468-001; LIFECYCLE_PHASE: Active; Lead Free Status: No; MFR_LIFECYCLE: Active; Manufacturer: Vishay; Manufacturer Part Num: CRCW04024K70FKED; Num Pins: 2; PART_SUBCLASS: RESISTORS; POWER: 1/16W; RoHS Compliant: Yes; TOLERANCE: 1%
C393 = CAP: CAPC,  X7R, 0402, 0.1uF, 25V, ±20%; AGILE_LINK: http://sj-agile9app/Agile/PLMServlet?action=OpenEmailObject&classid=10000&objid=213459527; Item Num: K13660-001; LIFECYCLE_PHASE: Active; Lead Free Status: Lead Free; MFR_LIFECYCLE: Active; Manufacturer: Murata; Manufacturer Part Num: GRM155R71E104KE14D; Num Pins: 2; PART_SUBCLASS: CAPACITORS; Part Class: CAPACITORS; RATED_VOLTAGE: 25V; RoHS Compliant: RoHS Compliant; TOLERANCE: +80%/-20%
R220 R221 = RES_0_OHM_5%_1_16W_0402_SMD: Item Num: H30887-001
C394 = CAP: CAP 10UF 10VDC X5R +/-15% 0603; IPN: xxxxxx-xxx; Item Num: J60031-001; Lead Free Status: No; Manufacturer: Murata; Manufacturer Part Num: GRM188R61A106KE69D; Num Pins: 2; Part Class: Capacitors; Price: 0; RoHS Compliant: Yes
C395 = CAP: CAP - CER, .47UF, 10V, X5R, 0402; AGILE_LINK: http://sj-agile9app/Agile/PLMServlet?action=OpenEmailObject&classid=10000&objid=256989651; IPN: xxxxxx-xxx; Item Num: H75789-001; LIFECYCLE_PHASE: Active; Lead Free Status: Lead Free; MFR_LIFECYCLE: Active; Manufacturer: Murata; Manufacturer Part Num: GRM155R61A474KE15D; Num Pins: 2; PART_SUBCLASS: CAPACITORS; Part Class: CAPACITORS; RATED_VOLTAGE: 10V; RoHS Compliant: RoHS Compliant; Tolerance: +80%/-20%
C396 C1271 = CAP: CAP - CER 4.7UF, +/-20%, 6.3V, X5R, 0402; Item Num: A36096-107; Manufacturer: Murata; Manufacturer Part Num: GRM155R60J475ME87D; Tolerance: +/-20%; Voltage: 6.3V
C397 C1043 C1272 C1273 C1279 C1280 = CAP: CAP - CER 1UF 6.3V 20% X5R 0201; Item Num: C83410-013; Lead Free Status: Yes; Manufacturer: TDK; Manufacturer Part Num: C0603X5R0J105M; Num Pins: 2; Part Class: CAPACITORS; RoHS Compliant: Yes
FB1 = BEAD_FERRITE_SM: FER-BEAD,0402,220.0OHM,580.0MA,+/-25%; Imax (A): 600mA; Item Num: A51464-023; Manufacturer: Murata Electronics; Manufacturer Part Num: BLM15AX221SN1D; Rdc (Ohms): 350mOhm; Tolerance (%): 25%
C404 C406-C411 C413 C414 = CAP: CAP CER 47UF 6.3V X5R 0603; Item Num: K31624-001; MFR_LIFECYCLE: Active; Manufacturer: Murata Electronics North America; Manufacturer Part Num: GRM188R60J476ME15D; Num Pins: 2; PART_SUBCLASS: CAPACITORS; RATED_VOLTAGE: 6.3V; RoHS Compliant: RoHS Compliant; TOLERANCE: 20%
C405 C412 C415 = CAP: CAP CER 22UF 6.3V X6S 0603; AGILE_LINK: http://sj-agile9app/Agile/PLMServlet?action=OpenEmailObject&classid=10000&objid=257560276; Item Num: H63299-001; LIFECYCLE_PHASE: Active; Lead Free Status: Not Lead Free; MFR_LIFECYCLE: Active; Manufacturer: Murata; Manufacturer Part Num: GRM188C80J226ME15D; Num Pins: 2; PART_SUBCLASS: CAPACITORS; RATED_VOLTAGE: 6.3V; RoHS Compliant: RoHS Compliant; TOLERANCE: 20%; Temperature Coefficient: X6S
FB30-FB33 FB41 = BEAD_FERRITE_SM: FERRITE BEAD 22 OHM 0603; Item Num: M16845-001; LIFECYCLE_PHASE: Active; MFR_LIFECYCLE: Active; Manufacturer: Murata; Manufacturer Part Num: BLM18SN220TZ1D; Num Pins: 2; PART_SUBCLASS: INDUCTORS; Part Class: Inductors; RoHS Compliant: Yes

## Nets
GND: C389.1 C390.2 C391.2 C392.2 C394.2 C395.2 C396.2 C397.2 C404.2 C405.1 C406.2 C407.2 C408.2 C409.2 C410.2 C411.2 C412.1 C413.2 C414.2 C415.1 C1043.1 C1271.2 C1272.1 C1273.1 C1279.1 C1280.1 C7397.2 C7398.2 J15.3 R190.2 R191.2 R204.1 R206.1 R207.1 R208.1 R210.1 R213.2 R216.1 R939.2 R941.2 R6280.1 R6306.2 R6308.2 R6316.2 U6.CR28(GND) U6.EP64(VCCEHT_FHT_GXFL_12A) U6.EP66(VCCEHT_FHT_GXFL_12A) U6.EU61(VCCERT1_FHT_GXFL_12A) U6.EU63(VCCEHT_FHT_GXFL_12A) U6.EU65(VCCEHT_FHT_GXFL_12A) U6.EY62(VCCERT1_FHT_GXFL_12A) U6.EY64(VCCEHT_FHT_GXFL_12A) U6.EY66(VCCEHT_FHT_GXFL_12A) U6.FC61(VCCERT1_FHT_GXFL_12A) U6.FF64(VCCERT1_FHT_GXFL_12A) U6.FF66(VCCERT2_FHT_GXFL_12A) U6.FJ61(VCCERT1_FHT_GXFL_12A) U6.FM32(VCCCLK_GXRR_15A) U6.FM62(VCCERT1_FHT_GXFL_12A) U6.FM64(VCCERT1_FHT_GXFL_12A) U6.FM66(VCCERT2_FHT_GXFL_12A) U6.FR31(VCCHFUSE_GXRR_15A) U6.FR33(VCCE_DTS_GXRR_15A) U6.FR61(VCCERT1_FHT_GXFL_12A) U6.FV30(VCCHFUSE_GXRR_15A) U6.FV32(VCCCLK_GXRR_15A) U6.FV34(VCCE_PLL_GXRR_15A) U6.GA29(VCCRT_GXRR_15A) U6.GA33(VCC_HSSI_GXRR_15A) U6.GD30(VCCRT_GXRR_15A) U6.GD34(VCC_HSSI_GXRR_15A) U6.GF29(VCCRT_GXRR_15A) U6.GF31(VCCRT_GXRR_15A) U6.GF33(VCC_HSSI_GXRR_15A) U6.GF35(VCC_HSSI_GXRR_15A) U6.GH30(VCCRT_GXRR_15A) U6.GH34(VCC_HSSI_GXRR_15A) U6.GL29(VCCRT_GXRR_15A) U6.GL31(VCCRT_GXRR_15A) U6.GL33(VCC_HSSI_GXRR_15A) U6.GL35(VCC_HSSI_GXRR_15A) U6.GP30(VCCRT_GXRR_15A) U6.GP32(VCCED_GXRR_15A) U6.GU29(VCCRT_GXRR_15A) U6.GV6(GND) U6.GV10(GND) U6.GV18(GND) U6.GV22(GND) U6.GW72(GND) U6.GW74(GND) U6.GW76(GND) U6.GW78(GND) U6.GW82(GND) U6.GY28(GND) U6.GY30(GND) U6.GY32(VCCED_GXRR_15A) U6.GY34(VCC_HSSI_GXRR_15A) U6.GY36(GND) U6.GY38(GND) U6.GY44(GND) U6.GY50(GND) U6.GY56(GND) U6.GY62(GND) U6.GY64(GND) U6.H4(GND) U6.HA8(GND) U6.HA12(GND) U6.HA20(GND) U6.HA24(GND) U6.HB73(GND) U6.HB75(GND) U6.HB79(GND) U6.HB81(GND) U6.HC29(VCCH_GXRR_15A) U6.HC31(VCCH_GXRR_15A) U6.HC33(VCC_HSSI_GXRR_15A) U6.HC35(VCC_HSSI_GXRR_15A) U6.HC39(GND) U6.HC45(GND) U6.HC51(GND) U6.HC63(GND) U6.HD1(GND) U6.HD6(GND) U6.HD14(GND) U6.HD18(GND) U6.HE72(GND) U6.HE74(GND) U6.HE78(GND) U6.HE80(GND) U6.HF28(GND) U6.HF30(VCCH_GXRR_15A) U6.HF32(GND) U6.HF34(VCC_HSSI_GXRR_15A) U6.HF40(GND) U6.HF46(GND) U6.HF52(GND) U6.HF60(GND) U6.HF66(GND) U6.HG3(GND) U6.HG12(GND) U6.HG16(GND) U6.HG24(GND) U6.HH75(GND) U6.HH77(GND) U6.HH81(GND) U6.HH83(GND) U6.HJ29(VCCH_GXRR_15A) U6.HJ31(GND) U6.HJ33(VCC_HSSI_GXRR_15A) U6.HJ35(GND) U6.HJ41(GND) U6.HJ47(GND) U6.HJ53(GND) U6.HJ57(GND) U6.HK6(GND) U6.HK10(GND) U6.HK18(GND) U6.HK22(GND) U6.HL72(GND) U6.HL76(GND) U6.HL78(GND) U6.HL82(GND) U6.HM28(GND) U6.HM30(VCCH_GXRR_15A) U6.HM32(GND) U6.HM34(GND) U6.HM36(GND) U6.HM42(GND) U6.HM48(GND) U6.HM54(GND) U6.HM62(GND) U6.HM66(GND) U6.HN8(GND) U6.HN12(GND) U6.HN20(GND) U6.HN24(GND) U6.HP75(GND) U6.HP79(GND) U6.HP81(GND) U6.HR29(VCCH_GXRR_15A) U6.HR31(VCCH_GXRR_15A) U6.HR33(GND) U6.HR35(GND) U6.HR37(GND) U6.HR43(GND) U6.HR49(GND) U6.HR55(GND) U6.HR59(GND) U6.HT1(GND) U6.HT6(GND) U6.HT14(GND) U6.HT18(GND) U6.HU72(GND) U6.HU78(GND) U6.HU80(GND) U6.HV26(GND) U6.HV28(GND) U6.HV30(GND) U6.HV36(GND) U6.HV38(GND) U6.HV58(GND) U6.HV66(GND) U6.HV70(GND) U6.HW3(GND) U6.HW12(GND) U6.HW16(GND) U6.HW24(GND) U6.HY29(GND) U6.HY63(GND) U6.HY65(GND) U6.J2(GND) U6.J65(GND) U6.JA75(GND) U6.JA77(GND) U6.JA81(GND) U6.JA83(GND) U6.JB30(GND) U6.JB36(GND) U6.JB38(GND) U6.JB40(GND) U6.JB42(GND) U6.JB44(GND) U6.JB46(GND) U6.JB48(GND) U6.JB50(GND) U6.JB52(GND) U6.JB54(GND) U6.JB56(GND) U6.JB58(GND) U6.JB60(GND) U6.JB66(GND) U6.JC6(GND) U6.JC10(GND) U6.JC18(GND) U6.JC22(GND) U6.JD72(GND) U6.JD76(GND) U6.JD78(GND) U6.JD82(GND) U6.JE37(GND) U6.JE61(GND) U6.JF8(GND) U6.JF12(GND) U6.JF20(GND) U6.JF24(GND) U6.JG73(GND) U6.JG75(GND) U6.JG79(GND) U6.JG81(GND) U6.JH28(GND) U6.JH30(GND) U6.JH32(GND) U6.JH34(GND) U6.JH36(GND) U6.JH38(GND) U6.JH40(GND) U6.JH42(GND) U6.JH44(GND) U6.JH46(GND) U6.JH48(GND) U6.JH50(GND) U6.JH52(GND) U6.JH54(GND) U6.JH56(GND) U6.JH58(GND) U6.JH66(GND) U6.JJ1(GND) U6.JJ6(GND) U6.JJ14(GND) U6.JJ18(GND) U6.JK72(GND) U6.JK74(GND) U6.JK78(GND) U6.JK80(GND) U6.JL68(GND) U6.JM3(GND) U6.JM12(GND) U6.JM16(GND) U6.JM24(GND) U6.JN75(GND) U6.JN77(GND) U6.JN81(GND) U6.JN83(GND) U6.JP38(GND) U6.JP40(GND) U6.JP42(GND) U6.JP44(GND) U6.JP46(GND) U6.JP48(GND) U6.JP50(GND) U6.JP52(GND) U6.JP54(GND) U6.JP56(GND) U6.JP58(GND) U6.JP60(GND) U6.JP62(GND) U6.JP64(GND) U6.JR6(GND) U6.JR10(GND) U6.JR18(GND) U6.JR22(GND) U6.JT72(GND) U6.JT76(GND) U6.JT78(GND) U6.JT82(GND) U6.JU27(GND) U6.JU29(GND) U6.JU31(GND) U6.JU33(GND) U6.JU35(GND) U6.JU37(GND) U6.JU68(GND) U6.JV8(GND) U6.JV12(GND) U6.JV20(GND) U6.JV24(GND) U6.JW73(GND) U6.JW75(GND) U6.JW79(GND) U6.JW81(GND) U6.JY38(GND) U6.JY56(GND) U6.JY58(GND) U6.JY70(GND) U6.K69(GND) U6.K72(GND) U6.K76(GND) U6.K78(GND) U6.K82(GND) U6.KA1(GND) U6.KA6(GND) U6.KA14(GND) U6.KA18(GND) U6.KB72(GND) U6.KB74(GND) U6.KB78(GND) U6.KB80(GND) U6.KC39(GND) U6.KC41(GND) U6.KC43(GND) U6.KC45(GND) U6.KC47(GND) U6.KC49(GND) U6.KC51(GND) U6.KC53(GND) U6.KC55(GND) U6.KC57(GND) U6.KC59(GND) U6.KC61(GND) U6.KC63(GND) U6.KC65(GND) U6.KD3(GND) U6.KD12(GND) U6.KD16(GND) U6.KD24(GND) U6.KE75(GND) U6.KE77(GND) U6.KE81(GND) U6.KE83(GND) U6.KF66(GND) U6.KG6(GND) U6.KG10(GND) U6.KG18(GND) U6.KG22(GND) U6.KH72(GND) U6.KH76(GND) U6.KH78(GND) U6.KH82(GND) U6.KJ68(GND) U6.KK8(GND) U6.KK12(GND) U6.KK20(GND) U6.KK24(GND) U6.KL73(GND) U6.KL75(GND) U6.KL79(GND) U6.KL81(GND) U6.KM26(GND) U6.KM28(GND) U6.KM30(GND) U6.KM32(GND) U6.KM34(GND) U6.KM36(GND) U6.KM38(GND) U6.KM40(GND) U6.KM42(GND) U6.KM44(GND) U6.KM46(GND) U6.KM48(GND) U6.KM50(GND) U6.KM52(GND) U6.KM54(GND) U6.KM56(GND) U6.KM58(GND) U6.KM60(GND) U6.KM62(GND) U6.KM64(GND) U6.KM66(GND) U6.KM70(GND) U6.KN1(GND) U6.KN6(GND) U6.KN14(GND) U6.KN18(GND) U6.KP72(GND) U6.KP74(GND) U6.KP78(GND) U6.KP80(GND) U6.KR68(VSIGN_0) U6.KT3(GND) U6.KT12(GND) U6.KT16(GND) U6.KT24(GND) U6.KU70(VSIGP_0) U6.KV75(GND) U6.KV77(GND) U6.KV81(GND) U6.KV83(GND) U6.KY6(GND) U6.KY10(GND) U6.KY18(GND) U6.KY22(GND) U6.LA72(GND) U6.LA76(GND) U6.LA78(GND) U6.LA82(GND) U6.LB70(VREFN_ADC) U6.LC8(GND) U6.LC12(GND) U6.LC20(GND) U6.LC24(GND) U6.LD73(GND) U6.LD75(GND) U6.LD79(GND) U6.LD81(GND) U6.LE27(GND) U6.LE29(GND) U6.LE31(GND) U6.LE33(GND) U6.LE35(GND) U6.LE37(GND) U6.LE39(GND) U6.LE41(GND) U6.LE43(GND) U6.LE45(GND) U6.LE47(GND) U6.LE49(GND) U6.LE51(GND) U6.LE53(GND) U6.LE55(GND) U6.LE57(GND) U6.LE59(GND) U6.LE61(GND) U6.LE63(GND) U6.LE65(GND) U6.LE68(GND) U6.LF1(GND) U6.LF6(GND) U6.LF14(GND) U6.LF18(GND) U6.LG72(GND) U6.LG74(GND) U6.LG78(GND) U6.LG80(GND) U6.LH66(VSIGN_1) U6.LJ3(GND) U6.LJ16(GND) U6.LK71(GND) U6.LK75(GND) U6.LK77(GND) U6.LK81(GND) U6.LK83(GND) U6.LL65(VSIGP_1) U6.LM69(GND) U6.LM72(GND) U6.LM76(GND) U6.LM78(GND) U6.LM82(GND) U6.LP67(GND) U6.LP73(GND) U6.LP75(GND) U6.LP79(GND) U6.LP81(GND) U6.LR2(GND) U6.LT69(GND) U6.LT72(GND) U6.LT74(GND) U6.LT78(GND) U6.LT80(GND) U6.LU7(GND) U6.LU11(GND) U6.LU15(GND) U6.LU19(GND) U6.LU23(GND) U6.LU26(GND) U6.LU28(GND) U6.LU30(GND) U6.LU32(GND) U6.LU34(GND) U6.LU36(GND) U6.LU38(GND) U6.LU40(GND) U6.LU42(GND) U6.LU44(GND) U6.LU46(GND) U6.LU48(GND) U6.LU50(GND) U6.LU52(GND) U6.LU54(GND) U6.LU56(GND) U6.LU58(GND) U6.LU60(GND) U6.LU62(GND) U6.LU64(GND) U6.LV67(GND) U6.LV71(GND) U6.LV75(GND) U6.LV77(GND) U6.LV81(GND) U6.LV83(GND) U6.LY69(GND) U6.LY72(GND) U6.LY76(GND) U6.LY78(GND) U6.LY82(GND) U6.M67(GND) U6.M73(GND) U6.M75(GND) U6.M79(GND) U6.M81(GND) U6.MB67(GND) U6.MB73(GND) U6.MB75(GND) U6.MB79(GND) U6.MB81(GND) U6.MB83(GND) U6.MC2(GND) U6.MD4(GND) U6.ME72(GND) U6.ME74(GND) U6.ME78(GND) U6.ME80(GND) U6.ME82(GND) U6.MF9(GND) U6.MF13(GND) U6.MF17(GND) U6.MF21(GND) U6.MF25(GND) U6.MF27(GND) U6.MF29(GND) U6.MF31(GND) U6.MF33(GND) U6.MF35(GND) U6.MF37(GND) U6.MF39(GND) U6.MF41(GND) U6.MF43(GND) U6.MF45(GND) U6.MF47(GND) U6.MF49(GND) U6.MF51(GND) U6.MF53(GND) U6.MF55(GND) U6.MF57(GND) U6.MF59(GND) U6.MF61(GND) U6.MF63(GND) U6.MF65(GND) U6.MG67(GND) U6.MG71(GND) U6.MG75(GND) U6.MG77(GND) U6.MG79(GND) U6.MG81(GND) U6.MG83(GND) U6.MH4(GND) U6.MJ69(GND) U6.MJ72(GND) U6.MJ76(GND) U6.MJ78(GND) U6.MJ80(GND) U6.MJ82(GND) U6.MK5(GND) U6.MK9(GND) U6.MK65(GND) U6.ML73(GND) U6.ML75(GND) U6.ML77(GND) U6.ML79(GND) U6.N65(GND) U6.P72(GND) U6.P74(GND) U6.P78(GND) U6.P80(GND) U6.R4(GND) U6.R7(GND) U6.R11(GND) U6.R15(GND) U6.R19(GND) U6.R23(GND) U6.R26(GND) U6.R28(GND) U6.R30(GND) U6.R32(GND) U6.R34(GND) U6.R36(GND) U6.R38(GND) U6.R40(GND) U6.R42(GND) U6.R44(GND) U6.R46(GND) U6.R48(GND) U6.R50(GND) U6.R52(GND) U6.R54(GND) U6.R56(GND) U6.R58(GND) U6.R60(GND) U6.R62(GND) U6.R64(GND) U6.T67(GND) U6.T71(GND) U6.T75(GND) U6.T77(GND) U6.T81(GND) U6.T83(GND) U6.U65(GND) U6.V69(GND) U6.V72(GND) U6.V76(GND) U6.V78(GND) U6.V82(GND) U6.Y67(GND) U6.Y71(GND) U6.Y73(GND) U6.Y75(GND) U6.Y79(GND) U6.Y81(GND) U19.3(GND) U21.2(GND) U36.B3(VSS) U104.B3(VSS) ; also on sheet 9 10 11 13 14 15 16 17 18 19 20 21 22 23 25 26 27 28 29 30 31 32 41 42 43 44 45 46 47 48 49 50 51 52 53 54 55 56 57 58 59 60 61 62 63 64 65 66 67 68 69 70 71 72 73 74 75 76 77
GNDSENSE: C393.1 R221.1 U6.FJ39(GNDSENSE)
VCCA_PLL_FLTR: U6.BM44(VCCA_PLL) U6.BM46(VCCA_PLL) U6.BM48(VCCA_PLL) U6.BM50(VCCA_PLL) U6.JY44(VCCA_PLL) U6.JY46(VCCA_PLL) U6.JY48(VCCA_PLL) U6.JY50(VCCA_PLL) ; also on sheet 59 75
VCCE_PLL_DTS_GXR: C396.1 C1271.1 U6.DJ33(VCCE_DTS_GXRR_15C) U6.DM34(VCCE_PLL_GXRR_15C) U6.ED60(VCCE_PLL_GXRL_14C) U6.EG61(VCCE_DTS_GXRL_14C) ; also on sheet 69
VCCFUSEWR_GXF: C397.1 C1043.2 U6.HC61(VCCFUSECORE_GXFL_12A) U6.HF62(VCCFUSEWR_GXFL_12A) ; also on sheet 74
VCCFUSEWR_SDM: U6.HF56(VCCFUSEWR_SDM) U6.HM56(VCCFUSEWR_SDM) ; also on sheet 69 76
VCCH_FGT_GXF: C407.1 C408.1 C409.1 FB30.1 FB41.1 U6.FV66(VCCH_FGT_GXFL_12A) U6.GA65(VCCH_FGT_GXFL_12A) U6.GD66(VCCH_FGT_GXFL_12A) U6.GF65(VCCH_FGT_GXFL_12A) U6.GH66(VCCH_FGT_GXFL_12A) U6.GP66(VCCH_FGT_GXFL_12A) U6.GU65(VCCH_FGT_GXFL_12A) U6.GY66(VCCH_FGT_GXFL_12A) ; also on sheet 76
VCCLSENSE: C393.2 R220.1 U6.FC39(VCCLSENSE)
VCCPLLDIG_HPS: C394.1 C395.1 FB1.2 U6.BV38(VCCPLLDIG_HPS) U6.CA39(VCCPLLDIG_HPS) ; also on sheet 76
VCCPLLDIG_SDM: U6.HY57(VCCPLLDIG_SDM) U6.JE57(VCCPLLDIG_SDM) ; also on sheet 65 76
VCCR_CORE: U6.CG41(VCCRCORE) U6.CG53(VCCRCORE) U6.CN41(VCCRCORE) U6.CN53(VCCRCORE) U6.CR54(VCCRCORE) U6.HY37(VCCRCORE) U6.HY39(VCCRCORE) U6.HY51(VCCRCORE) U6.JE39(VCCRCORE) U6.JE51(VCCRCORE) ; also on sheet 59 75
0p6V_VREF_DDR4_CH01: U6.BM40(VREFB3DN0) U6.BM42(VREFB3CN0) U6.BM52(VREFB3BN0) U6.BM54(VREFB3AN0) ; also on sheet 9 10 11 14 15 16 72 76
0p6V_VREF_DDR4_CH2: U6.JY40(VREFB2CN0) U6.JY42(VREFB2FN0) ; also on sheet 20 72 76
0p6V_VREF_DDR4_CH3: U6.JY52(VREFB2EN0) U6.JY54(VREFB2BN0) ; also on sheet 19 72 76
0p8V_VCC_HSSI_GXF: U6.EP60(VCC_HSSI_GXFL_12A) U6.EU59(VCC_HSSI_GXFL_12A) U6.FC59(VCC_HSSI_GXFL_12A) U6.FF58(VCC_HSSI_GXFL_12A) U6.FF60(VCC_HSSI_GXFL_12A) U6.FJ59(VCC_HSSI_GXFL_12A) U6.FM58(VCC_HSSI_GXFL_12A) U6.FV58(VCC_HSSI_GXFL_12A) U6.GA59(VCC_HSSI_GXFL_12A) U6.GD58(VCC_HSSI_GXFL_12A) U6.GD60(VCC_HSSI_GXFL_12A) U6.GF59(VCC_HSSI_GXFL_12A) U6.GH60(VCC_HSSI_GXFL_12A) U6.GL59(VCC_HSSI_GXFL_12A) U6.GP58(VCC_HSSI_GXFL_12A) U6.GP60(VCC_HSSI_GXFL_12A) U6.GY58(VCC_HSSI_GXFL_12A) U6.GY60(VCC_HSSI_GXFL_12A) U6.HY53(VCCL_SDM) U6.HY55(VCCL_SDM) U6.JE53(VCCL_SDM) U6.JE55(VCCL_SDM) ; also on sheet 65 75
0p8V_VCCH: U6.CY58(VCCH) U6.DF36(VCCH) U6.DM58(VCCH) U6.DV36(VCCH) U6.ED58(VCCH) U6.EJ36(VCCH) U6.EP58(VCCH) U6.EY36(VCCH) U6.FJ57(VCCH) U6.FM36(VCCH) U6.GA57(VCCH) U6.GD36(VCCH) U6.GL57(VCCH) U6.GP36(VCCH) U6.HC57(VCCH) U6.HF36(VCCH) U6.HV54(VCCH_SDM) ; also on sheet 64 75 77
0p9V_VCC_HSSI_GXR: U6.CN61(VCC_HSSI_GXRL_14C) U6.CR60(VCC_HSSI_GXRL_14C) U6.CU59(VCC_HSSI_GXRL_14C) U6.CU61(VCC_HSSI_GXRL_14C) U6.CY60(VCC_HSSI_GXRL_14C) U6.DJ59(VCC_HSSI_GXRL_14C) U6.DJ61(VCC_HSSI_GXRL_14C) U6.DM60(VCC_HSSI_GXRL_14C) U6.DR33(VCC_HSSI_GXRR_15C) U6.DR59(VCC_HSSI_GXRL_14C) U6.DR61(VCC_HSSI_GXRL_14C) U6.DV34(VCC_HSSI_GXRR_15C) U6.DV60(VCC_HSSI_GXRL_14C) U6.EA33(VCC_HSSI_GXRR_15C) U6.EA35(VCC_HSSI_GXRR_15C) U6.EA61(VCC_HSSI_GXRL_14C) U6.ED34(VCC_HSSI_GXRR_15C) U6.EG33(VCC_HSSI_GXRR_15C) U6.EG35(VCC_HSSI_GXRR_15C) U6.EP34(VCC_HSSI_GXRR_15C) U6.EU33(VCC_HSSI_GXRR_15C) U6.EU35(VCC_HSSI_GXRR_15C) U6.EY34(VCC_HSSI_GXRR_15C) U6.FC33(VCC_HSSI_GXRR_15C) ; also on sheet 63 75 77
0p9V_VCCED_GXR: U6.CY62(VCCED_GXRL_14C) U6.DF62(VCCED_GXRL_14C) U6.EJ32(VCCED_GXRR_15C) U6.EP32(VCCED_GXRR_15C) ; also on sheet 60 75
0p9V_VCCL_HPS: FB1.1 U6.CG39(VCCL_HPS) U6.CN37(VCCL_HPS) U6.CN39(VCCL_HPS) U6.CU37(VCCL_HPS) U6.CU39(VCCL_HPS) ; also on sheet 60 75
1p0V_VCCCLK_GXR: C389.2 R195.2 R927.2 R6325.2 U6.DF32(VCCCLK_GXRR_15C) U6.DM32(VCCCLK_GXRR_15C) U6.ED62(VCCCLK_GXRL_14C) U6.EJ62(VCCCLK_GXRL_14C) U19.5(VCC) ; also on sheet 31 74 76
1p0V_VCCERT_FGT_GXF: U6.FR63(VCCERT_FGT_GXFL_12A) U6.GA63(VCCERT_FGT_GXFL_12A) U6.GD62(VCCERT_FGT_GXFL_12A) U6.GD64(VCCERT_FGT_GXFL_12A) U6.GL63(VCCERT_FGT_GXFL_12A) U6.GP62(VCCERT_FGT_GXFL_12A) U6.GP64(VCCERT_FGT_GXFL_12A) U6.GU63(VCCERT_FGT_GXFL_12A) ; also on sheet 61 75
1p0V_VCCFUSE_GXR: C1279.2 C1280.2 U6.DJ31(VCCHFUSE_GXRR_15C) U6.DM30(VCCHFUSE_GXRR_15C) U6.ED64(VCCHFUSE_GXRL_14C) U6.EG63(VCCHFUSE_GXRL_14C) ; also on sheet 74
1p0V_VCCRT_GXR: U6.DC65(VCCRT_GXRL_14C) U6.DF64(VCCRT_GXRL_14C) U6.DJ63(VCCRT_GXRL_14C) U6.DJ65(VCCRT_GXRL_14C) U6.DM64(VCCRT_GXRL_14C) U6.DR29(VCCRT_GXRR_15C) U6.DR63(VCCRT_GXRL_14C) U6.DR65(VCCRT_GXRL_14C) U6.DV30(VCCRT_GXRR_15C) U6.DV64(VCCRT_GXRL_14C) U6.EA29(VCCRT_GXRR_15C) U6.EA31(VCCRT_GXRR_15C) U6.EA65(VCCRT_GXRL_14C) U6.ED30(VCCRT_GXRR_15C) U6.EG29(VCCRT_GXRR_15C) U6.EG31(VCCRT_GXRR_15C) U6.EJ30(VCCRT_GXRR_15C) U6.EL29(VCCRT_GXRR_15C) ; also on sheet 62 75 77
1p2V_DDR4_CH01: U6.BR41(VCCIO_PIO_3D) U6.BR43(VCCIO_PIO_3D) U6.BR45(VCCIO_PIO_3C) U6.BR47(VCCIO_PIO_3C) U6.BR49(VCCIO_PIO_3B) U6.BR51(VCCIO_PIO_3B) U6.BR53(VCCIO_PIO_3A) U6.BR55(VCCIO_PIO_3A) U6.CA41(VCCIO_PIO_3D) U6.CA43(VCCIO_PIO_3D) U6.CA45(VCCIO_PIO_3C) U6.CA47(VCCIO_PIO_3C) U6.CA49(VCCIO_PIO_3B) U6.CA51(VCCIO_PIO_3B) U6.CA53(VCCIO_PIO_3A) U6.CA55(VCCIO_PIO_3A) U6.HV56(VCCIO_PIO_SDM) ; also on sheet 9 10 11 14 15 16 32 46 47 52 70 72 76 77
1p2V_DDR4_CH2: U6.JL39(VCCIO_PIO_2C) U6.JL41(VCCIO_PIO_2C) U6.JL43(VCCIO_PIO_2F) U6.JL45(VCCIO_PIO_2F) U6.JL47(VCCIO_PIO_2E) U6.JL49(VCCIO_PIO_2E) U6.JL51(VCCIO_PIO_2B) U6.JL53(VCCIO_PIO_2B) U6.JU39(VCCIO_PIO_2C) U6.JU41(VCCIO_PIO_2C) U6.JU43(VCCIO_PIO_2F) U6.JU45(VCCIO_PIO_2F) U6.JU47(VCCIO_PIO_2E) U6.JU49(VCCIO_PIO_2E) U6.JU51(VCCIO_PIO_2B) U6.JU53(VCCIO_PIO_2B) ; also on sheet 19 20 30 71 72 76
1p8V: FB30.2 FB31.2 FB32.2 FB33.2 FB41.2 U6.CR44(VCCPT) U6.CR46(VCCPT) U6.CR48(VCCPT) U6.CR50(VCCPT) U6.HV44(VCCPT) U6.HV46(VCCPT) U6.HV48(VCCPT) U6.HV50(VCCPT) ; also on sheet 66 76
1p8V_FLTR: C404.1 C405.2 C406.1 FB31.1 U6.BM38(VCCPLL_HPS) U6.BR39(VCCPLL_HPS) U6.HY59(VCCPLL_SDM) U6.JE59(VCCPLL_SDM) U6.JL59(VCCADC) U6.JU59(VCCADC) ; also on sheet 76
1p8v_MAIN_I2C_SCL: U6.N17(HPS_IOB_8,_GPIO1_IO7,_SPIS1_MISO,_UART1_RX,_I2C1_SCL,_NAND_CLE,_EMAC1_RXD1) ; also on sheet 50 77
1p8v_MAIN_I2C_SDA: U6.AD26(HPS_IOB_7,_GPIO1_IO6,_SPIS1_SS0_N,_UART1_TX,_I2C1_SDA,_NAND_ADQ3,_EMAC1_RXD0) ; also on sheet 49 77
1p8V_PRE: C390.1 C391.1 C7397.1 C7398.1 R211.2 R212.2 R2699.2 R2700.2 U36.B4(VCC) U104.B4(VCC) ; also on sheet 49 50 51 68
1p8V_VCCCLK_GXF: C413.1 C414.1 C415.2 C1272.2 C1273.2 FB33.1 U6.HC65(VCCCLK_GXFL_12A) U6.HF64(VCCCLK_GXFL_12A) ; also on sheet 28 29
1p8V_VCCH_GXR: C410.1 C411.1 C412.2 FB32.1 U6.CG63(VCCH_GXRL_14C) U6.CG65(VCCH_GXRL_14C) U6.CK64(VCCH_GXRL_14C) U6.CN65(VCCH_GXRL_14C) U6.CR64(VCCH_GXRL_14C) U6.CU63(VCCH_GXRL_14C) U6.CU65(VCCH_GXRL_14C) U6.EU29(VCCH_GXRR_15C) U6.EU31(VCCH_GXRR_15C) U6.EY30(VCCH_GXRR_15C) U6.FC29(VCCH_GXRR_15C) U6.FF30(VCCH_GXRR_15C) U6.FJ29(VCCH_GXRR_15C) U6.FJ31(VCCH_GXRR_15C) ; also on sheet 75
AVST8_CLK: U6.MD64(SDM_IO14,_AVSTX8_CLK,_PWRMGT_SCL) ; also on sheet 50
AVST8_DATA0: U6.LN62(SDM_IO2,_AVSTX8_DATA0,_AS_CLK,_SDMMC_CFG_DATA0) ; also on sheet 50
AVST8_DATA1: U6.KR63(SDM_IO4,_AVSTX8_DATA1,_AS_DATA0,_SDMMC_CFG_CMD) ; also on sheet 50
AVST8_DATA2: U6.LR63(SDM_IO1,_AVSTX8_DATA2,_AS_DATA1,_SDMMC_CFG_DATA1) ; also on sheet 50
AVST8_DATA3: U6.MA64(SDM_IO3,_AVSTX8_DATA3,_AS_DATA2,_SDMMC_CFG_DATA2) ; also on sheet 50
AVST8_DATA4: U6.LW63(SDM_IO6,_AVSTX8_DATA4,_AS_DATA3,_SDMMC_CFG_DATA3) ; also on sheet 49
AVST8_DATA5: U6.MA62(SDM_IO13,_AVSTX8_DATA5,_SDMMC_CFG_DATA5) ; also on sheet 50
AVST8_DATA6: U6.KW63(SDM_IO15,_AVSTX8_DATA6,_SDMMC_CFG_DATA6) ; also on sheet 50
AVST8_DATA7: U6.KU62(SDM_IO10,_AVSTX8_DATA7,_SDMMC_CFG_DATA7) ; also on sheet 50
AVST8_READY: U6.KJ63(SDM_IO8,_AVSTX8_READY,_AS_NCSO3,_SDMMC_CFG_DATA4) ; also on sheet 50
AVST8_VALID_HPS_RSTn: R6280.2 U6.MC65(SDM_IO11,_AVSTX8_VALID,_PWRMGT_SDA) ; also on sheet 50
CXL_PERSTn: U19.2(A) ; also on sheet 32 48 52
CXL_RX_N0: U6.AH10(GXRR15C_RX_CH0N) ; also on sheet 32
CXL_RX_N1: U6.AU3(GXRR15C_RX_CH1N) ; also on sheet 32
CXL_RX_N2: U6.BA10(GXRR15C_RX_CH2N) ; also on sheet 32
CXL_RX_N3: U6.BK3(GXRR15C_RX_CH3N) ; also on sheet 32
CXL_RX_N4: U6.BN10(GXRR15C_RX_CH4N) ; also on sheet 32
CXL_RX_N5: U6.CB3(GXRR15C_RX_CH5N) ; also on sheet 32
CXL_RX_N6: U6.CE10(GXRR15C_RX_CH6N) ; also on sheet 32
CXL_RX_N7: U6.CP3(GXRR15C_RX_CH7N) ; also on sheet 32
CXL_RX_N8: U6.CV10(GXRR15C_RX_CH8N) ; also on sheet 32
CXL_RX_N9: U6.DG3(GXRR15C_RX_CH9N) ; also on sheet 32
CXL_RX_N10: U6.DK10(GXRR15C_RX_CH10N) ; also on sheet 32
CXL_RX_N11: U6.DW3(GXRR15C_RX_CH11N) ; also on sheet 32
CXL_RX_N12: U6.EB10(GXRR15C_RX_CH12N) ; also on sheet 32
CXL_RX_N13: U6.EM3(GXRR15C_RX_CH13N) ; also on sheet 32
CXL_RX_N14: U6.ER10(GXRR15C_RX_CH14N) ; also on sheet 32
CXL_RX_N15: U6.FD3(GXRR15C_RX_CH15N) ; also on sheet 32
CXL_RX_P0: U6.AL8(GXRR15C_RX_CH0P) ; also on sheet 32
CXL_RX_P1: U6.AP1(GXRR15C_RX_CH1P) ; also on sheet 32
CXL_RX_P2: U6.BD8(GXRR15C_RX_CH2P) ; also on sheet 32
CXL_RX_P3: U6.BG1(GXRR15C_RX_CH3P) ; also on sheet 32
CXL_RX_P4: U6.BT8(GXRR15C_RX_CH4P) ; also on sheet 32
CXL_RX_P5: U6.BW1(GXRR15C_RX_CH5P) ; also on sheet 32
CXL_RX_P6: U6.CH8(GXRR15C_RX_CH6P) ; also on sheet 32
CXL_RX_P7: U6.CL1(GXRR15C_RX_CH7P) ; also on sheet 32
CXL_RX_P8: U6.DA8(GXRR15C_RX_CH8P) ; also on sheet 32
CXL_RX_P9: U6.DD1(GXRR15C_RX_CH9P) ; also on sheet 32
CXL_RX_P10: U6.DN8(GXRR15C_RX_CH10P) ; also on sheet 32
CXL_RX_P11: U6.DT1(GXRR15C_RX_CH11P) ; also on sheet 32
CXL_RX_P12: U6.EE8(GXRR15C_RX_CH12P) ; also on sheet 32
CXL_RX_P13: U6.EH1(GXRR15C_RX_CH13P) ; also on sheet 32
CXL_RX_P14: U6.EV8(GXRR15C_RX_CH14P) ; also on sheet 32
CXL_RX_P15: U6.FA1(GXRR15C_RX_CH15P) ; also on sheet 32
CXL_TX_N0: U6.AH22(GXRR15C_TX_CH0N) ; also on sheet 32
CXL_TX_N1: U6.AU16(GXRR15C_TX_CH1N) ; also on sheet 32
CXL_TX_N2: U6.BA22(GXRR15C_TX_CH2N) ; also on sheet 32
CXL_TX_N3: U6.BK16(GXRR15C_TX_CH3N) ; also on sheet 32
CXL_TX_N4: U6.BN22(GXRR15C_TX_CH4N) ; also on sheet 32
CXL_TX_N5: U6.CB16(GXRR15C_TX_CH5N) ; also on sheet 32
CXL_TX_N6: U6.CE22(GXRR15C_TX_CH6N) ; also on sheet 32
CXL_TX_N7: U6.CP16(GXRR15C_TX_CH7N) ; also on sheet 32
CXL_TX_N8: U6.CV22(GXRR15C_TX_CH8N) ; also on sheet 32
CXL_TX_N9: U6.DG16(GXRR15C_TX_CH9N) ; also on sheet 32
CXL_TX_N10: U6.DK22(GXRR15C_TX_CH10N) ; also on sheet 32
CXL_TX_N11: U6.DW16(GXRR15C_TX_CH11N) ; also on sheet 32
CXL_TX_N12: U6.EB22(GXRR15C_TX_CH12N) ; also on sheet 32
CXL_TX_N13: U6.EM16(GXRR15C_TX_CH13N) ; also on sheet 32
CXL_TX_N14: U6.ER22(GXRR15C_TX_CH14N) ; also on sheet 32
CXL_TX_N15: U6.FD16(GXRR15C_TX_CH15N) ; also on sheet 32
CXL_TX_P0: U6.AL20(GXRR15C_TX_CH0P) ; also on sheet 32
CXL_TX_P1: U6.AP14(GXRR15C_TX_CH1P) ; also on sheet 32
CXL_TX_P2: U6.BD20(GXRR15C_TX_CH2P) ; also on sheet 32
CXL_TX_P3: U6.BG14(GXRR15C_TX_CH3P) ; also on sheet 32
CXL_TX_P4: U6.BT20(GXRR15C_TX_CH4P) ; also on sheet 32
CXL_TX_P5: U6.BW14(GXRR15C_TX_CH5P) ; also on sheet 32
CXL_TX_P6: U6.CH20(GXRR15C_TX_CH6P) ; also on sheet 32
CXL_TX_P7: U6.CL14(GXRR15C_TX_CH7P) ; also on sheet 32
CXL_TX_P8: U6.DA20(GXRR15C_TX_CH8P) ; also on sheet 32
CXL_TX_P9: U6.DD14(GXRR15C_TX_CH9P) ; also on sheet 32
CXL_TX_P10: U6.DN20(GXRR15C_TX_CH10P) ; also on sheet 32
CXL_TX_P11: U6.DT14(GXRR15C_TX_CH11P) ; also on sheet 32
CXL_TX_P12: U6.EE20(GXRR15C_TX_CH12P) ; also on sheet 32
CXL_TX_P13: U6.EH14(GXRR15C_TX_CH13P) ; also on sheet 32
CXL_TX_P14: U6.EV20(GXRR15C_TX_CH14P) ; also on sheet 32
CXL_TX_P15: U6.FA14(GXRR15C_TX_CH15P) ; also on sheet 32
FM41_15C_CXL_PERSTN: R6299.1 R6325.1 ; also on sheet 29
FPGA_CONF_DONE: R219.2 U6.LW61(SDM_IO16,_PWRMGT_SDA) ; also on sheet 48 50
FPGA_CXL_PERSTN: R195.1 R196.2 U6.CY30(I_PIN_PERST_N_15C_GXR)
FPGA_JTAG_TCK: R216.2 U6.LB64(TCK) ; also on sheet 50
FPGA_JTAG_TDI: R215.2 U6.LN64(TDI) ; also on sheet 50
FPGA_JTAG_TDO: U6.LB66(TDO) ; also on sheet 50
FPGA_JTAG_TMS: R214.2 U6.LR65(TMS) ; also on sheet 50
FPGA_MSEL0: R203.1 ; also on sheet 50
FPGA_MSEL1: R205.1 ; also on sheet 50
FPGA_NCONFIG: R218.2 U6.LR61(NCONFIG) ; also on sheet 49
FPGA_NSTATUS: R217.2 U6.LH62(NSTATUS) ; also on sheet 50
FPGA_OSC_CLK_1: U6.KU64(OSC_CLK_1) ; also on sheet 43
FPGA_SDM_SCL: U6.ML71(SDM_IO0,_PWRMGT_SCL) ; also on sheet 46
FPGA_SDM_SDA: U6.ML67(SDM_IO12,_PWRMGT_SDA) ; also on sheet 46
FPGA_TEMP0An: U6.LH64(TEMPDIODE0AN) ; also on sheet 52
FPGA_TEMP0Ap: U6.LL63(TEMPDIODE0AP) ; also on sheet 52
FPGA_TEMP4n: U6.JE27(TEMPDIODE4N) ; also on sheet 52
FPGA_TEMP4p: U6.HY27(TEMPDIODE4P) ; also on sheet 52
FPGA_TEMP6n: U6.FJ27(TEMPDIODE6N) ; also on sheet 52
FPGA_TEMP6p: U6.FF26(TEMPDIODE6P) ; also on sheet 52
FPGA_VCC: U6.CG43(VCCP) U6.CG45(VCCP) U6.CG47(VCCP) U6.CG49(VCCP) U6.CG51(VCCP) U6.CN43(VCCP) U6.CN45(VCCP) U6.CN47(VCCP) U6.CN49(VCCP) U6.CN51(VCCP) U6.CR40(VCC) U6.CR42(VCC) U6.CU41(VCC) U6.CU43(VCC) U6.CU47(VCC) U6.CU49(VCC) U6.CU53(VCC) U6.CU55(VCC) U6.CY38(VCC) U6.CY42(VCC) U6.CY44(VCC) U6.CY48(VCC) U6.CY50(VCC) U6.CY54(VCC) U6.CY56(VCC) U6.DC39(VCC) U6.DC43(VCC) U6.DC45(VCC) U6.DC49(VCC) U6.DC51(VCC) U6.DC55(VCC) U6.DC57(VCC) U6.DF38(VCC) U6.DF40(VCC) U6.DF44(VCC) U6.DF46(VCC) U6.DF50(VCC) U6.DF52(VCC) U6.DF56(VCC) U6.DJ39(VCC) U6.DJ41(VCC) U6.DJ45(VCC) U6.DJ47(VCC) U6.DJ51(VCC) U6.DJ53(VCC) U6.DJ57(VCC) U6.DM40(VCC) U6.DM42(VCC) U6.DM46(VCC) U6.DM48(VCC) U6.DM52(VCC) U6.DM54(VCC) U6.DR37(VCC) U6.DR53(VCC) U6.DR55(VCC) U6.DV38(VCC) U6.DV40(VCC) U6.DV54(VCC) U6.DV56(VCC) U6.EA37(VCC) U6.EA39(VCC) U6.EA53(VCC) U6.EA55(VCC) U6.EA57(VCC) U6.ED38(VCC) U6.ED40(VCC) U6.ED56(VCC) U6.EG39(VCC) U6.EG53(VCC) U6.EG57(VCC) U6.EJ40(VCC) U6.EJ54(VCC) U6.EL37(VCC) U6.EL53(VCC) U6.EL55(VCC) U6.EP38(VCC) U6.EP40(VCC) U6.EP54(VCC) U6.EP56(VCC) U6.EU37(VCC) U6.EU39(VCC) U6.EU53(VCC) U6.EU55(VCC) U6.EU57(VCC) U6.EY38(VCC) U6.EY40(VCC) U6.EY56(VCC) U6.FC53(VCC) U6.FC57(VCC) U6.FF40(VCC) U6.FF54(VCC) U6.FJ37(VCC) U6.FJ53(VCC) U6.FJ55(VCC) U6.FM38(VCC) U6.FM40(VCC) U6.FM54(VCC) U6.FM56(VCC) U6.FR37(VCC) U6.FR39(VCC) U6.FR53(VCC) U6.FR55(VCC) U6.FV38(VCC) U6.FV40(VCC) U6.FV56(VCC) U6.GA39(VCC) U6.GA53(VCC) U6.GD40(VCC) U6.GD54(VCC) U6.GF37(VCC) U6.GF53(VCC) U6.GF55(VCC) U6.GH38(VCC) U6.GH40(VCC) U6.GH54(VCC) U6.GH56(VCC) U6.GL37(VCC) U6.GL39(VCC) U6.GL53(VCC) U6.GL55(VCC) U6.GP38(VCC) U6.GP40(VCC) U6.GP56(VCC) U6.GU39(VCC) U6.GU53(VCC) U6.GY40(VCC) U6.GY42(VCC) U6.GY46(VCC) U6.GY48(VCC) U6.GY52(VCC) U6.GY54(VCC) U6.HC37(VCC) U6.HC41(VCC) U6.HC43(VCC) U6.HC47(VCC) U6.HC49(VCC) U6.HC53(VCC) U6.HC55(VCC) U6.HF38(VCC) U6.HF42(VCC) U6.HF44(VCC) U6.HF48(VCC) U6.HF50(VCC) U6.HF54(VCC) U6.HJ37(VCC) U6.HJ39(VCC) U6.HJ43(VCC) U6.HJ45(VCC) U6.HJ49(VCC) U6.HJ51(VCC) U6.HJ55(VCC) U6.HM38(VCC) U6.HM40(VCC) U6.HM44(VCC) U6.HM46(VCC) U6.HM50(VCC) U6.HM52(VCC) U6.HR39(VCC) U6.HR41(VCC) U6.HR45(VCC) U6.HR47(VCC) U6.HR51(VCC) U6.HR53(VCC) U6.HV40(VCC) U6.HV42(VCC) U6.HV52(VCC) U6.HY41(VCCP) U6.HY43(VCCP) U6.HY45(VCCP) U6.HY47(VCCP) U6.HY49(VCCP) U6.JE41(VCCP) U6.JE43(VCCP) U6.JE45(VCCP) U6.JE47(VCCP) U6.JE49(VCCP) ; also on sheet 55 56 75 77
HPS_JTAG_TCK: U6.BM30(HPS_IOB_9,_GPIO1_IO8,_JTAG_TCK,_SPIS0_CLK,_MDIO2_MDIO,_I2C_EMAC2_SDA,_NAND_ADQ4,_EMAC1_TXD2) ; also on sheet 49
HPS_JTAG_TDI: U6.U21(HPS_IOB_12,_GPIO1_IO11,_JTAG_TDI,_SPIS0_MISO,_MDIO0_MDC,_I2C_EMAC0_SCL,_NAND_ADQ7,_EMAC1_RXD3) ; also on sheet 50
HPS_JTAG_TDO: U6.BJ29(HPS_IOB_11,_GPIO1_IO10,_JTAG_TDO,_SPIS0_SS0_N,_MDIO0_MDIO,_I2C_EMAC0_SDA,_NAND_ADQ6,_EMAC1_RXD2) ; also on sheet 50
HPS_JTAG_TMS: U6.L19(HPS_IOB_10,_GPIO1_IO9,_JTAG_TMS,_SPIS0_MOSI,_MDIO2_MDC,_I2C_EMAC2_SCL,_NAND_ADQ5,_EMAC1_TXD3) ; also on sheet 49
HPS_OSC_CLK: U6.U25(HPS_IOB_20,_GPIO1_IO19,_SPIM0_SS0_N,_MDIO1_MDC,_I2C_EMAC1_SCL,_NAND_ADQ11,_SDMMC_DATA5,_EMAC2_RXD1) ; also on sheet 43
HPS_UART_RX: J15.2 R6286.1 U6.L15(HPS_IOB_4,_GPIO1_IO3,_SPIM1_SS0_N,_UART0_RX,_I2C0_SCL,_NAND_RE_N,_EMAC1_RX_CTL)
HPS_UART_TX: J15.1 R6285.1 U6.BF26(HPS_IOB_3,_GPIO1_IO2,_SPIM1_MISO,_UART0_TX,_I2C0_SDA,_NAND_WE_N,_EMAC1_RX_CLK)
IO_1p8V: R198.2 R199.2 R200.2 R201.2 R209.1 R214.1 R215.1 R217.1 R218.1 R219.1 R6285.2 R6286.2 U6.BV36(VCCIO_HPS) U6.CA37(VCCIO_HPS) U6.CG37(VCCIO_HPS) U6.JL55(VCCIO_SDM) U6.JL57(VCCBAT) U6.JU55(VCCIO_SDM) U6.JU57(VCCBAT) ; also on sheet 43 44 46 67 75 77
MSEL0: R199.1 R203.2 SW2.1(A1) U6.LB62(SDM_IO5,_AS_NCSO0,_SDMMC_CFG_CCLK,_MSEL0)
MSEL1: R200.1 R205.2 SW2.2(A2) U6.MH64(SDM_IO7,_AS_NCSO2,_MSEL1)
MSEL2: R201.1 R202.2 SW2.3(A3)
MSEL2_FPGA_nCATTrip: R202.1 U6.LW65(SDM_IO9,_AS_NCSO1,_MSEL2) ; also on sheet 49
QSPI_1_M10_CLK: U36.B2(C) ; also on sheet 50
QSPI_1_M10_CS_N: R211.1 U36.C2(S#) ; also on sheet 49
QSPI_1_M10_DATA0: U36.D3(DQ0) ; also on sheet 50
QSPI_1_M10_DATA1: U36.D2(DQ1) ; also on sheet 50
QSPI_1_M10_DATA2: U36.C4(W#/DQ2) ; also on sheet 50
QSPI_1_M10_DATA3: U36.D4(DQ3) ; also on sheet 50
QSPI_1_M10_RESETN: R212.1 U36.A4(RESET#/DNU) ; also on sheet 50
QSPI_2_M10_CLK: U104.B2(C) ; also on sheet 50
QSPI_2_M10_CS_N: R2699.1 U104.C2(S#) ; also on sheet 50
QSPI_2_M10_DATA0: U104.D3(DQ0) ; also on sheet 50
QSPI_2_M10_DATA1: U104.D2(DQ1) ; also on sheet 50
QSPI_2_M10_DATA2: U104.C4(W#/DQ2) ; also on sheet 50
QSPI_2_M10_DATA3: U104.D4(DQ3) ; also on sheet 50
QSPI_2_M10_RESETN: R2700.1 U104.A4(RESET#/DNU) ; also on sheet 50
QSPI_AVST_SEL: R198.1 SW2.4(A4) ; also on sheet 50
RCOMP_FM41_BANK_15A: R6307.2 R6308.1 U6.HR27(GND)
REFCLK_CXL_15C_CH0_N: R190.1 U6.ED26(REFCLK_GXRR15C_CH0N) ; also on sheet 45
REFCLK_CXL_15C_CH0_P: R939.1 U6.EG27(REFCLK_GXRR15C_CH0P) ; also on sheet 45
REFCLK_CXL_15C_CH1_N: R191.1 U6.EY26(REFCLK_GXRR15C_CH1N) ; also on sheet 45
REFCLK_CXL_15C_CH1_P: R941.1 U6.FC27(REFCLK_GXRR15C_CH1P) ; also on sheet 45
REFCLK_FM41_15C_CXL_P: R6316.1 U6.JH26(GND) ; also on sheet 45
VSENSE0+: R220.2 ; also on sheet 54 55
VSENSE0-: R221.2 ; also on sheet 54 55
N36112579: R207.2 SW2.6(B3)
N36112582: R206.2 SW2.7(B2)
N36112585: R204.2 SW2.8(B1)
N40033287: R210.2 U6.LP71(RREF_SDM)
N40033916: C392.1 R209.2 R213.1 U6.KW68(VREFP_ADC) U21.1(VO)
N40168095: R194.2 U6.EP26(15C_GXR_IO_RCOMP_N_0)
N40168098: R194.1 U6.EU27(15C_GXR_IO_RCOMP_P_0)
N40355462: R208.2 SW2.5(B4)
N40460971: R197.1 U6.GL27(15A_GXR_IO_RCOMP_P_0)
N40460975: R197.2 U6.GH26(15A_GXR_IO_RCOMP_N_0)
N44631565: R927.1 U19.1(OE)
N51913133: R196.1 R6299.2 U19.4(Y)
N51917930: R6306.1 R6307.1 U6.HM26(GND)

Not connected (* = marked no-connect by the designer): U6 AB1(HPS_IOA_12,_GPIO0_IO11,_SPIM1_SS0_N,_SPIS1_MISO,_MDIO0_MDC,_I2C_EMAC0_SCL,_NAND_ADQ7,_USB0_DATA7)* AB6(HPS_IOA_8,_GPIO0_IO7,_SPIM0_SS0_N,_MDIO2_MDC,_UART1_RX,_I2C_EMAC2_SCL,_NAND_CLE,_USB0_DATA3,_SDMMC_DATA5)* AB14(HPS_IOA_6,_GPIO0_IO5,_SPIM0_MOSI,_UART1_RTS_N,_I2C0_SCL,_NAND_ADQ2,_USB0_NXT,_SDMMC_DATA3)* AB18(HPS_IOA_2,_GPIO0_IO1,_SPIM1_SS1_N,_SPIS0_MOSI,_UART0_RTS_N,_NAND_ADQ1,_USB0_STP,_SDMMC_CMD)* AE3(HPS_IOA_10,_GPIO0_IO9,_SPIM1_MOSI,_SPIS1_MOSI,_MDIO1_MDC,_I2C_EMAC1_SCL,_NAND_ADQ5,_USB0_DATA5,_SDMMC_DATA7)* AE16(HPS_IOA_4,_GPIO0_IO3,_SPIS0_MISO,_UART0_RX,_I2C1_SCL,_NAND_RE_N,_USB0_DATA0,_SDMMC_DATA1)* AT26(HPS_IOB_5,_GPIO1_IO4,_SPIM1_SS1_N,_SPIS1_CLK,_UART1_CTS_N,_NAND_WP_N,_EMAC1_TXD0)* BJ27(HPS_IOB_1,_GPIO1_IO0,_SPIM1_CLK,_UART0_CTS_N,_NAND_ADQ0,_EMAC1_TX_CLK)* BJ31(HPS_IOB_23,_GPIO1_IO22,_SPIM0_MISO,_SPIS1_SS0_N,_MDIO0_MDIO,_I2C_EMAC0_SDA,_NAND_ADQ14,_EMAC2_RXD2)* BJ33(HPS_IOA_3,_GPIO0_IO2,_SPIS0_SS0_N,_UART0_TX,_I2C1_SDA,_NAND_WE_N,_USB0_DIR,_SDMMC_DATA0)* BM26(HPS_IOA_5,_GPIO0_IO4,_SPIM0_CLK,_UART1_CTS_N,_I2C0_SDA,_NAND_WP_N,_USB0_DATA1,_SDMMC_DATA2)* BM28(HPS_IOA_23,_GPIO0_IO22,_SPIM1_MISO,_SPIS0_SS0_N,_UART0_TX,_I2C0_SDA,_NAND_ADQ14,_USB1_DATA6,_EMAC0_RXD2)* BM32(HPS_IOB_21,_GPIO1_IO20,_SPIM0_CLK,_SPIS1_CLK,_I2C_EMAC2_SDA,_NAND_ADQ12,_SDMMC_DATA6,_EMAC2_TXD2)* BM34(HPS_IOA_1,_GPIO0_IO0,_SPIM0_SS1_N,_SPIS0_CLK,_UART0_CTS_N,_NAND_ADQ0,_USB0_CLK,_SDMMC_CCLK)* BV26(HPS_IOA_21,_GPIO0_IO20,_SPIM1_CLK,_SPIS0_CLK,_UART0_CTS_N,_I2C1_SDA,_NAND_ADQ12,_USB1_DATA4,_EMAC0_TXD2)* BV28(HPS_IOA_11,_GPIO0_IO10,_SPIM1_MISO,_SPIS1_SS0_N,_MDIO0_MDIO,_I2C_EMAC0_SDA,_NAND_ADQ6,_USB0_DATA6)* BV30(HPS_IOA_15,_GPIO0_IO14,_NAND_CE_N,_USB1_DIR,_EMAC0_RX_CLK)* BV32(HPS_IOA_19,_GPIO0_IO18,_NAND_ADQ10,_USB1_DATA2,_EMAC0_RXD0)* BV34(DNU5)* CA27(HPS_IOA_9,_GPIO0_IO8,_SPIM1_CLK,_SPIS1_CLK,_MDIO1_MDIO,_I2C_EMAC1_SDA,_NAND_ADQ4,_USB0_DATA4,_SDMMC_DATA6)* CA29(HPS_IOA_13,_GPIO0_IO12,_NAND_ALE,_USB1_CLK,_EMAC0_TX_CLK)* CA31(HPS_IOA_17,_GPIO0_IO16,_NAND_ADQ8,_USB1_DATA1,_EMAC0_TXD0)* CA33(DNU6)* CD26(HPS_IOA_20,_GPIO0_IO19,_SPIM1_SS1_N,_NAND_ADQ11,_USB1_DATA3,_EMAC0_RXD1)* CD28(HPS_IOA_7,_GPIO0_IO6,_SPIM0_MISO,_MDIO2_MDIO,_UART1_TX,_I2C_EMAC2_SDA,_NAND_ADQ3,_USB0_DATA2,_SDMMC_DATA4)* CG27(HPS_IOA_16,_GPIO0_IO15,_USB1_DATA0,_EMAC0_RX_CTL)* CG33(DNU75)* CN27(HPS_IOA_14,_GPIO0_IO13,_NAND_RB,_USB1_STP,_EMAC0_TX_CTL)* CN29(DNU70)* CU27(DNU67)* CY26(DNU72)* CY28(DNU77)* CY70(VCCEHT_PG1_GXRL_14C)* D7(HPS_IOA_22,_GPIO0_IO21,_SPIM1_MOSI,_SPIS0_MOSI,_UART0_RTS_N,_I2C1_SCL,_NAND_ADQ13,_USB1_DATA5,_EMAC0_TXD3)* DC27(DNU73)* DC29(DNU71)* DC68(VCCEHT_PG0_GXRL_14C)* DF28(DNU74)* DR27(DNU76)* DV26(VCCEHT_PG0_GXRR_15C)* EA27(VCCEHT_PG1_GXRR_15C)* EJ26(DNU68)* EL27(DNU69)* FG10(GXRR15A_RX_CH0N)* FG22(GXRR15A_TX_CH0N)* FK8(GXRR15A_RX_CH0P)* FK20(GXRR15A_TX_CH0P)* FN1(GXRR15A_RX_CH1P)* FN14(GXRR15A_TX_CH1P)* FT3(GXRR15A_RX_CH1N)* FT16(GXRR15A_TX_CH1N)* FV26(REFCLK_GXRR15A_CH0N)* FW10(GXRR15A_RX_CH2N)* FW22(GXRR15A_TX_CH2N)* GA27(REFCLK_GXRR15A_CH0P)* GB8(GXRR15A_RX_CH2P)* GB20(GXRR15A_TX_CH2P)* GD26(DNU62)* GE1(GXRR15A_RX_CH3P)* GE14(GXRR15A_TX_CH3P)* GF27(DNU61)* GJ3(GXRR15A_RX_CH3N)* GJ16(GXRR15A_TX_CH3N)* GM10(GXRR15A_RX_CH4N)* GM22(GXRR15A_TX_CH4N)* GP26(DNU57)* GR8(GXRR15A_RX_CH4P)* GR20(GXRR15A_TX_CH4P)* GU27(DNU58)* GV1(GXRR15A_RX_CH5P)* GV14(GXRR15A_TX_CH5P)* GY26(REFCLK_GXRR15A_CH1P)* HA3(GXRR15A_RX_CH5N)* HA16(GXRR15A_TX_CH5N)* HC27(REFCLK_GXRR15A_CH1N)* HD10(GXRR15A_RX_CH6N)* HD22(GXRR15A_TX_CH6N)* HF26(VCCEHT_PG0_GXRR_15A)* HG8(GXRR15A_RX_CH6P)* HG20(GXRR15A_TX_CH6P)* HJ27(VCCEHT_PG1_GXRR_15A)* HK1(GXRR15A_RX_CH7P)* HK14(GXRR15A_TX_CH7P)* HN3(GXRR15A_RX_CH7N)* HN16(GXRR15A_TX_CH7N)* HT10(GXRR15A_RX_CH8N)* HT22(GXRR15A_TX_CH8N)* HW8(GXRR15A_RX_CH8P)* HW20(GXRR15A_TX_CH8P)* HY31(DNU60)* HY33(I_PIN_PERST_N_15A_GXR)* J5(HPS_IOA_18,_GPIO0_IO17,_NAND_ADQ9,_USB1_NXT,_EMAC0_TXD1)* JB28(DNU65)* JB32(DNU66)* JB34(DNU63)* JC1(GXRR15A_RX_CH9P)* JC14(GXRR15A_TX_CH9P)* JE29(DNU56)* JE31(DNU59)* JE33(DNU64)* JF3(GXRR15A_RX_CH9N)* JF16(GXRR15A_TX_CH9N)* JJ10(GXRR15A_RX_CH10N)* JJ22(GXRR15A_TX_CH10N)* JM8(GXRR15A_RX_CH10P)* JM20(GXRR15A_TX_CH10P)* JR1(GXRR15A_RX_CH11P)* JR14(GXRR15A_TX_CH11P)* JV3(GXRR15A_RX_CH11N)* JV16(GXRR15A_TX_CH11N)* KA10(GXRR15A_RX_CH12N)* KA22(GXRR15A_TX_CH12N)* KD8(GXRR15A_RX_CH12P)* KD20(GXRR15A_TX_CH12P)* KG1(GXRR15A_RX_CH13P)* KG14(GXRR15A_TX_CH13P)* KJ65(DNU4)* KK3(GXRR15A_RX_CH13N)* KK16(GXRR15A_TX_CH13N)* KN10(GXRR15A_RX_CH14N)* KN22(GXRR15A_TX_CH14N)* KR65(DNU1)* KT8(GXRR15A_RX_CH14P)* KT20(GXRR15A_TX_CH14P)* KU66(DNU2)* KW65(DNU3)* KY1(GXRR15A_RX_CH15P)* KY14(GXRR15A_TX_CH15P)* L23(HPS_IOB_16,_GPIO1_IO15,_UART1_RX,_SDMMC_DATA1,_EMAC2_RX_CTL)* L26(HPS_IOB_24,_GPIO1_IO23,_SPIM0_SS0_N,_SPIS1_MISO,_MDIO0_MDC,_I2C_EMAC0_SCL,_NAND_ADQ15,_EMAC2_RXD3)* L28(HPS_IOB_13,_GPIO1_IO12,_I2C1_SDA,_NAND_ALE,_SDMMC_DATA0,_EMAC2_TX_CLK)* LC3(GXRR15A_RX_CH15N)* LC16(GXRR15A_TX_CH15N)* N13(HPS_IOB_2,_GPIO1_IO1,_SPIM1_MOSI,_UART0_RTS_N,_NAND_ADQ1,_EMAC1_TX_CTL)* N21(HPS_IOB_14,_GPIO1_IO13,_I2C1_SCL,_NAND_RB,_SDMMC_CMD,_EMAC2_TX_CTL)* N25(HPS_IOB_22,_GPIO1_IO21,_SPIM0_MOSI,_SPIS1_MOSI,_I2C_EMAC2_SCL,_NAND_ADQ13,_SDMMC_DATA7,_EMAC2_TXD3)* N27(HPS_IOB_15,_GPIO1_IO14,_UART1_TX,_NAND_CE_N,_SDMMC_CCLK,_EMAC2_RX_CLK)* U13(HPS_IOA_24,_GPIO0_IO23,_SPIM1_SS0_N,_SPIS0_MISO,_UART0_RX,_I2C0_SCL,_NAND_ADQ15,_USB1_DATA7,_EMAC0_RXD3)* U17(HPS_IOB_6,_GPIO1_IO5,_SPIS1_MOSI,_UART1_RTS_N,_NAND_ADQ2,_EMAC1_TXD1)* U27(HPS_IOB_17,_GPIO1_IO16,_UART1_CTS_N,_NAND_ADQ8,_SDMMC_DATA2,_EMAC2_TXD0)* W26(HPS_IOB_18,_GPIO1_IO17,_SPIM0_SS1_N,_UART1_RTS_N,_NAND_ADQ9,_SDMMC_DATA3,_EMAC2_TXD1)* W28(HPS_IOB_19,_GPIO1_IO18,_SPIM0_MISO,_MDIO1_MDIO,_I2C_EMAC1_SDA,_NAND_ADQ10,_SDMMC_DATA4,_EMAC2_RXD0)*; U21 3(NC)*; U36 A2(DNU1)* A3(DNU2)* A5(DNU3)* B1(DNU4)* B5(DNU5)* C1(DNU6)* C3(DNU7)* C5(DNU8)* D1(DNU9)* D5(DNU10)* E1(DNU11)* E2(DNU12)* E3(DNU13)* E4(DNU14)* E5(DNU15)*; U104 A2(DNU1)* A3(DNU2)* A5(DNU3)* B1(DNU4)* B5(DNU5)* C1(DNU6)* C3(DNU7)* C5(DNU8)* D1(DNU9)* D5(DNU10)* E1(DNU11)* E2(DNU12)* E3(DNU13)* E4(DNU14)* E5(DNU15)*

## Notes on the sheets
sheet 33
- R-TILE BANK 15C
sheet 34
- R-TILE BANK 15A
sheet 35
- SDM & Configuration
- Config Mode         MSEL2     MSEL1     MSEL0
    JTAG               1                 1                1
   AVST x8           1                 1               0
- Close = 0,  Open = 1
- 2Gbit Flash
- 1.7V - 2.0V
  Absmax = 4V
- 2Gb Serial Flash
- Layout Note: place it near to max10
- 2Gbit Flash
- 1.7V - 2.0V
  Absmax = 4V
- 2Gb Serial Flash
- Layout Note: place it near to max10
sheet 36
- Bank HPS&NC
sheet 37
- FPGA Power 1
sheet 38
- FPGA Power 2
- 0.9V
- Note: connect to GND as default
- (Group2)
- 1.0V
- 0.9V
- 0.9V
- 0.9V
- (Group1)
- 1.8V
- 1.8V
- (Group2)
- 0.8V
- 0.8V
- (Group2)
- RevA = 0.9V
- RevB = 0.8V
- FM67 - NC
- (Group1)
- 1.0V
- 1.0V
- Rev A , 0.95V
- Rev B, 0.9V
- (Group1)
- (Group1)
- Place caps under FPGA pins
- (Group2)
- (Group1)
- 1.0V
- 0.8V
- 1.0V
- 1.0V
- (Group2)
- 1.8V
- Place caps under FPGA pins
- 1.0V
- (Group1)
- Place caps under FPGA pins
- VCCN1V_IO_GXR
- (Group2)
sheet 39
- FPGA Power 3
- 1.8V
- 1.2V
- Filter for VCCADC
- VCCPLL_HPS
- VCCPLL_SDM
- RevA - 1.8V
- RevB - 1.2V
- FM67 -NC
- 1.2V
- RevA - 1.8V
- RevB - 1.2V
- 1.8V
- 1.8V
- 1.8V
- 1.8V
- 0.6V
- 0.6V
- 0.6V
- 2.4V
sheet 40
- FPGA GND 1
